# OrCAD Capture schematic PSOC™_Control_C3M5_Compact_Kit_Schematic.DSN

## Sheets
1 07. Revision History: title: KIT_PSC3M5_2GO; rev: 02; note: 630-60706-01
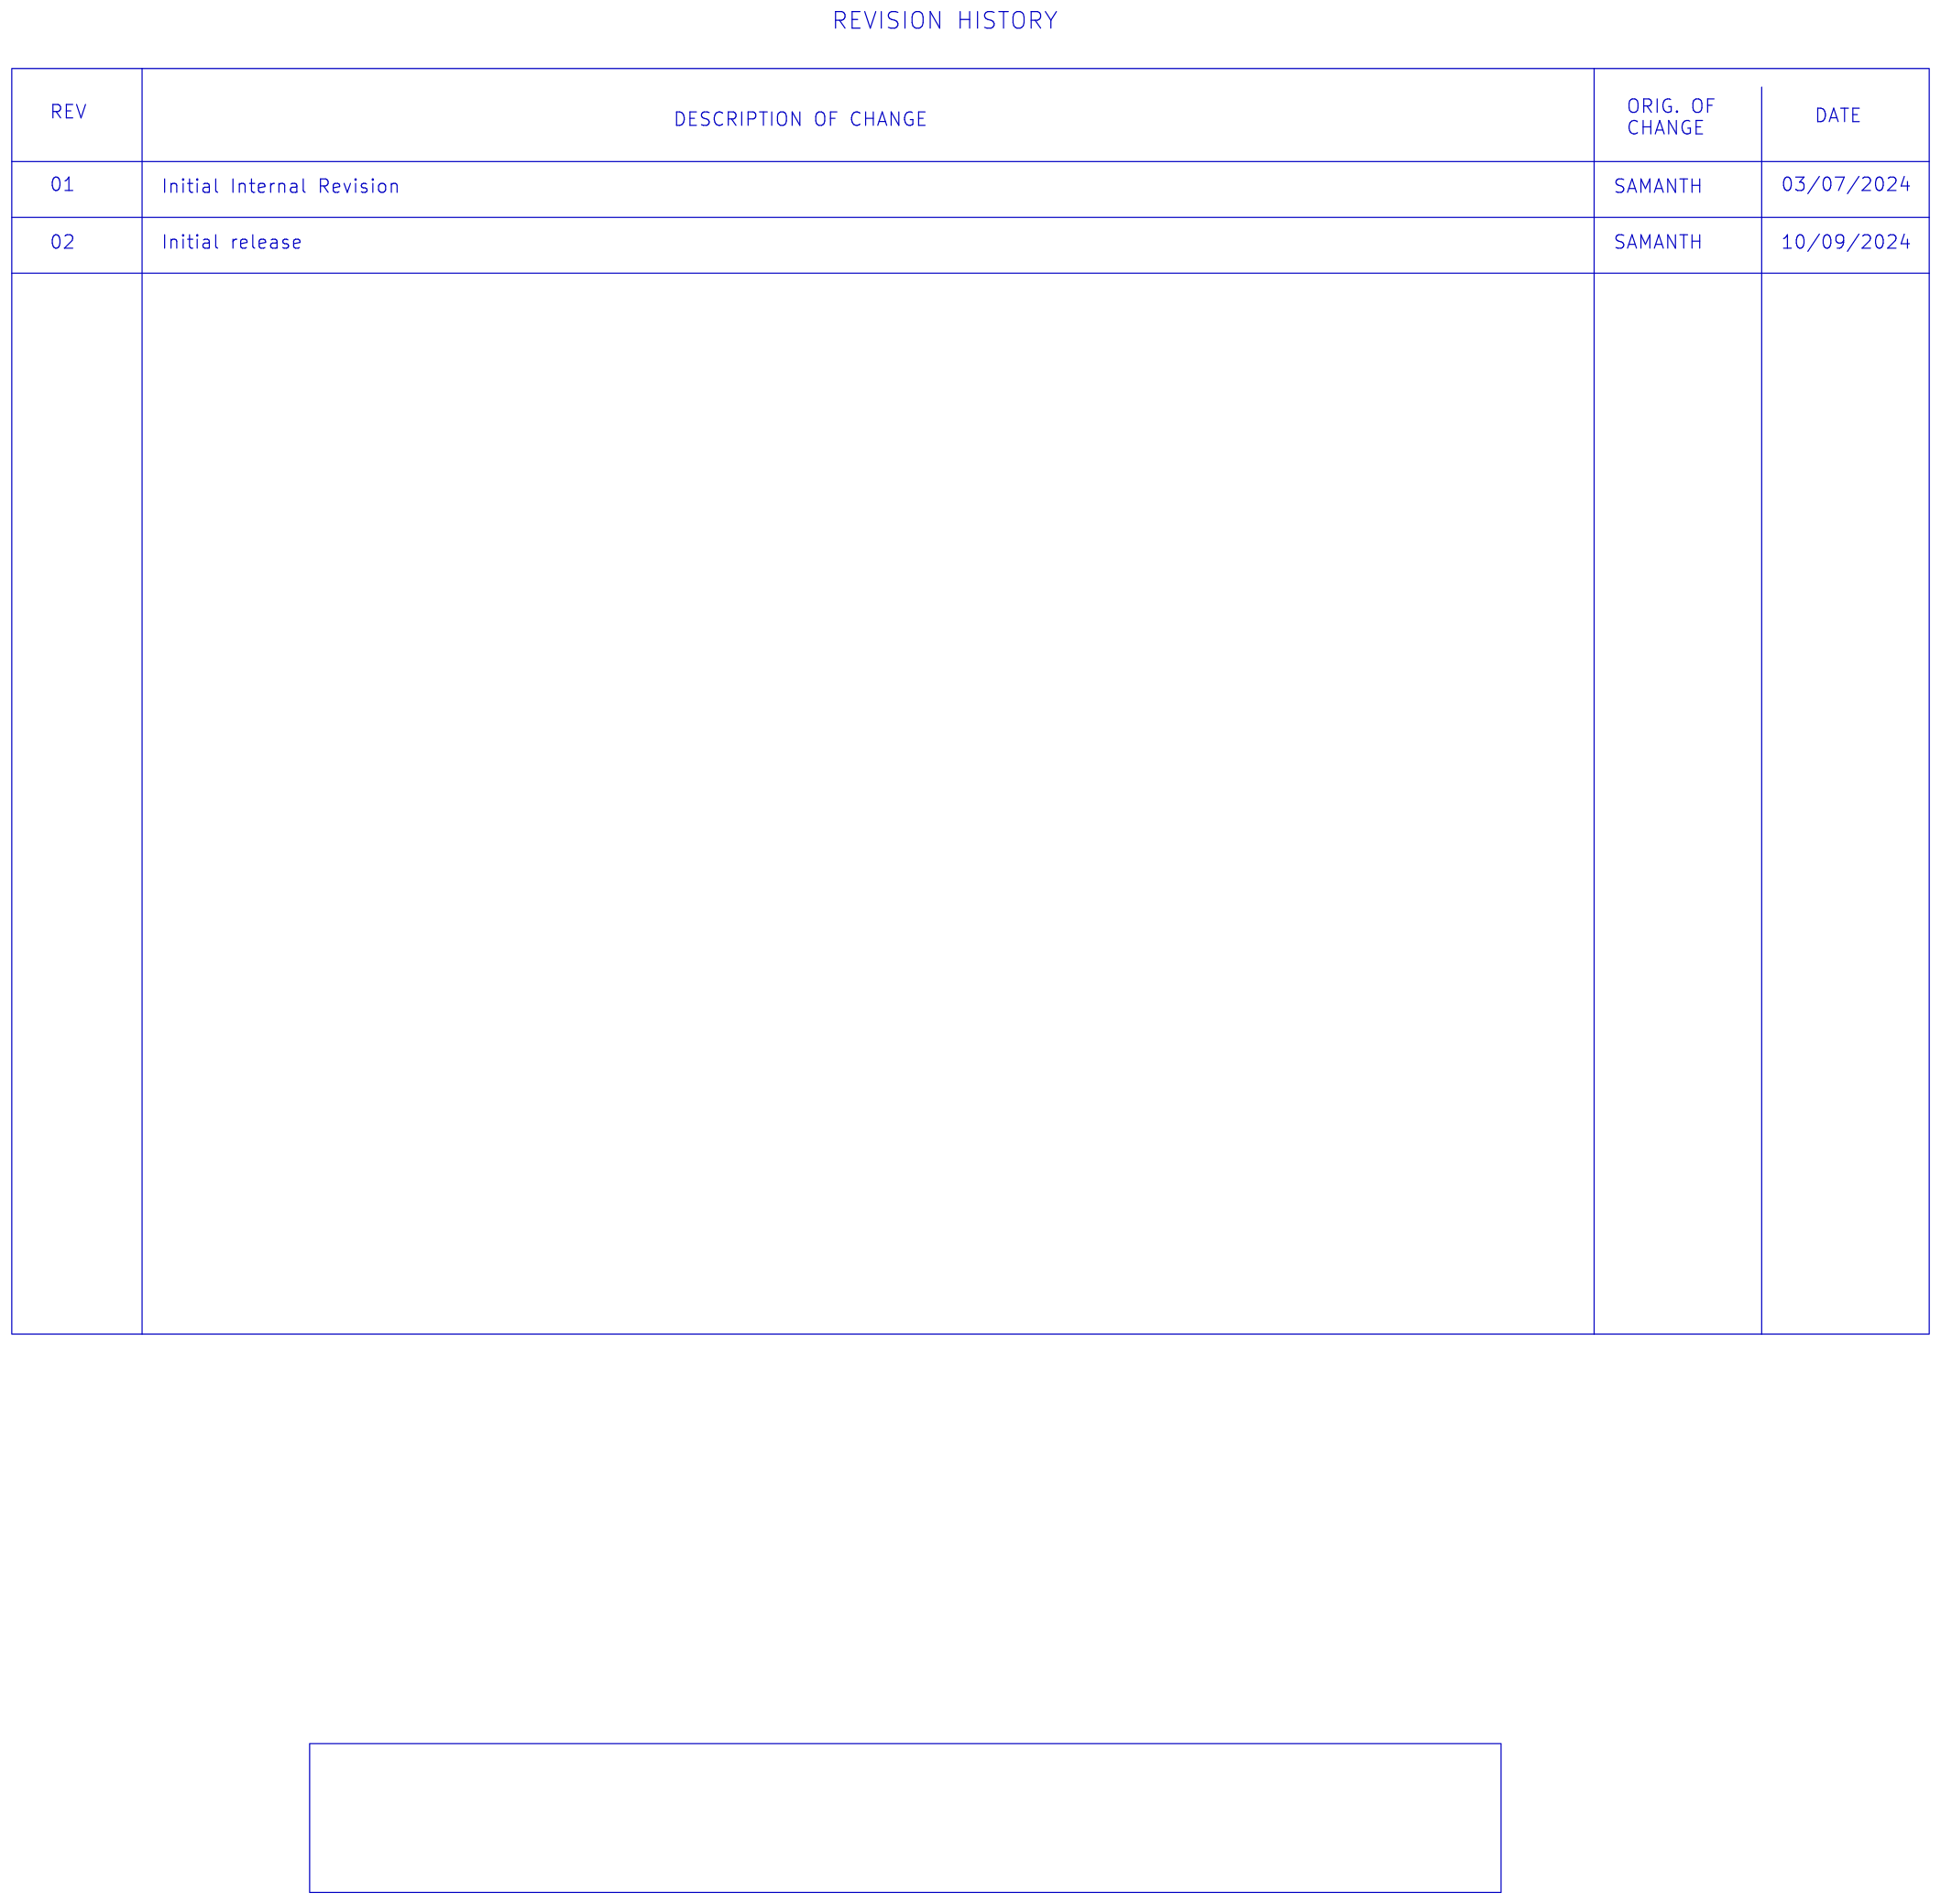
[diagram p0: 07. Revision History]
2 06. Accessories
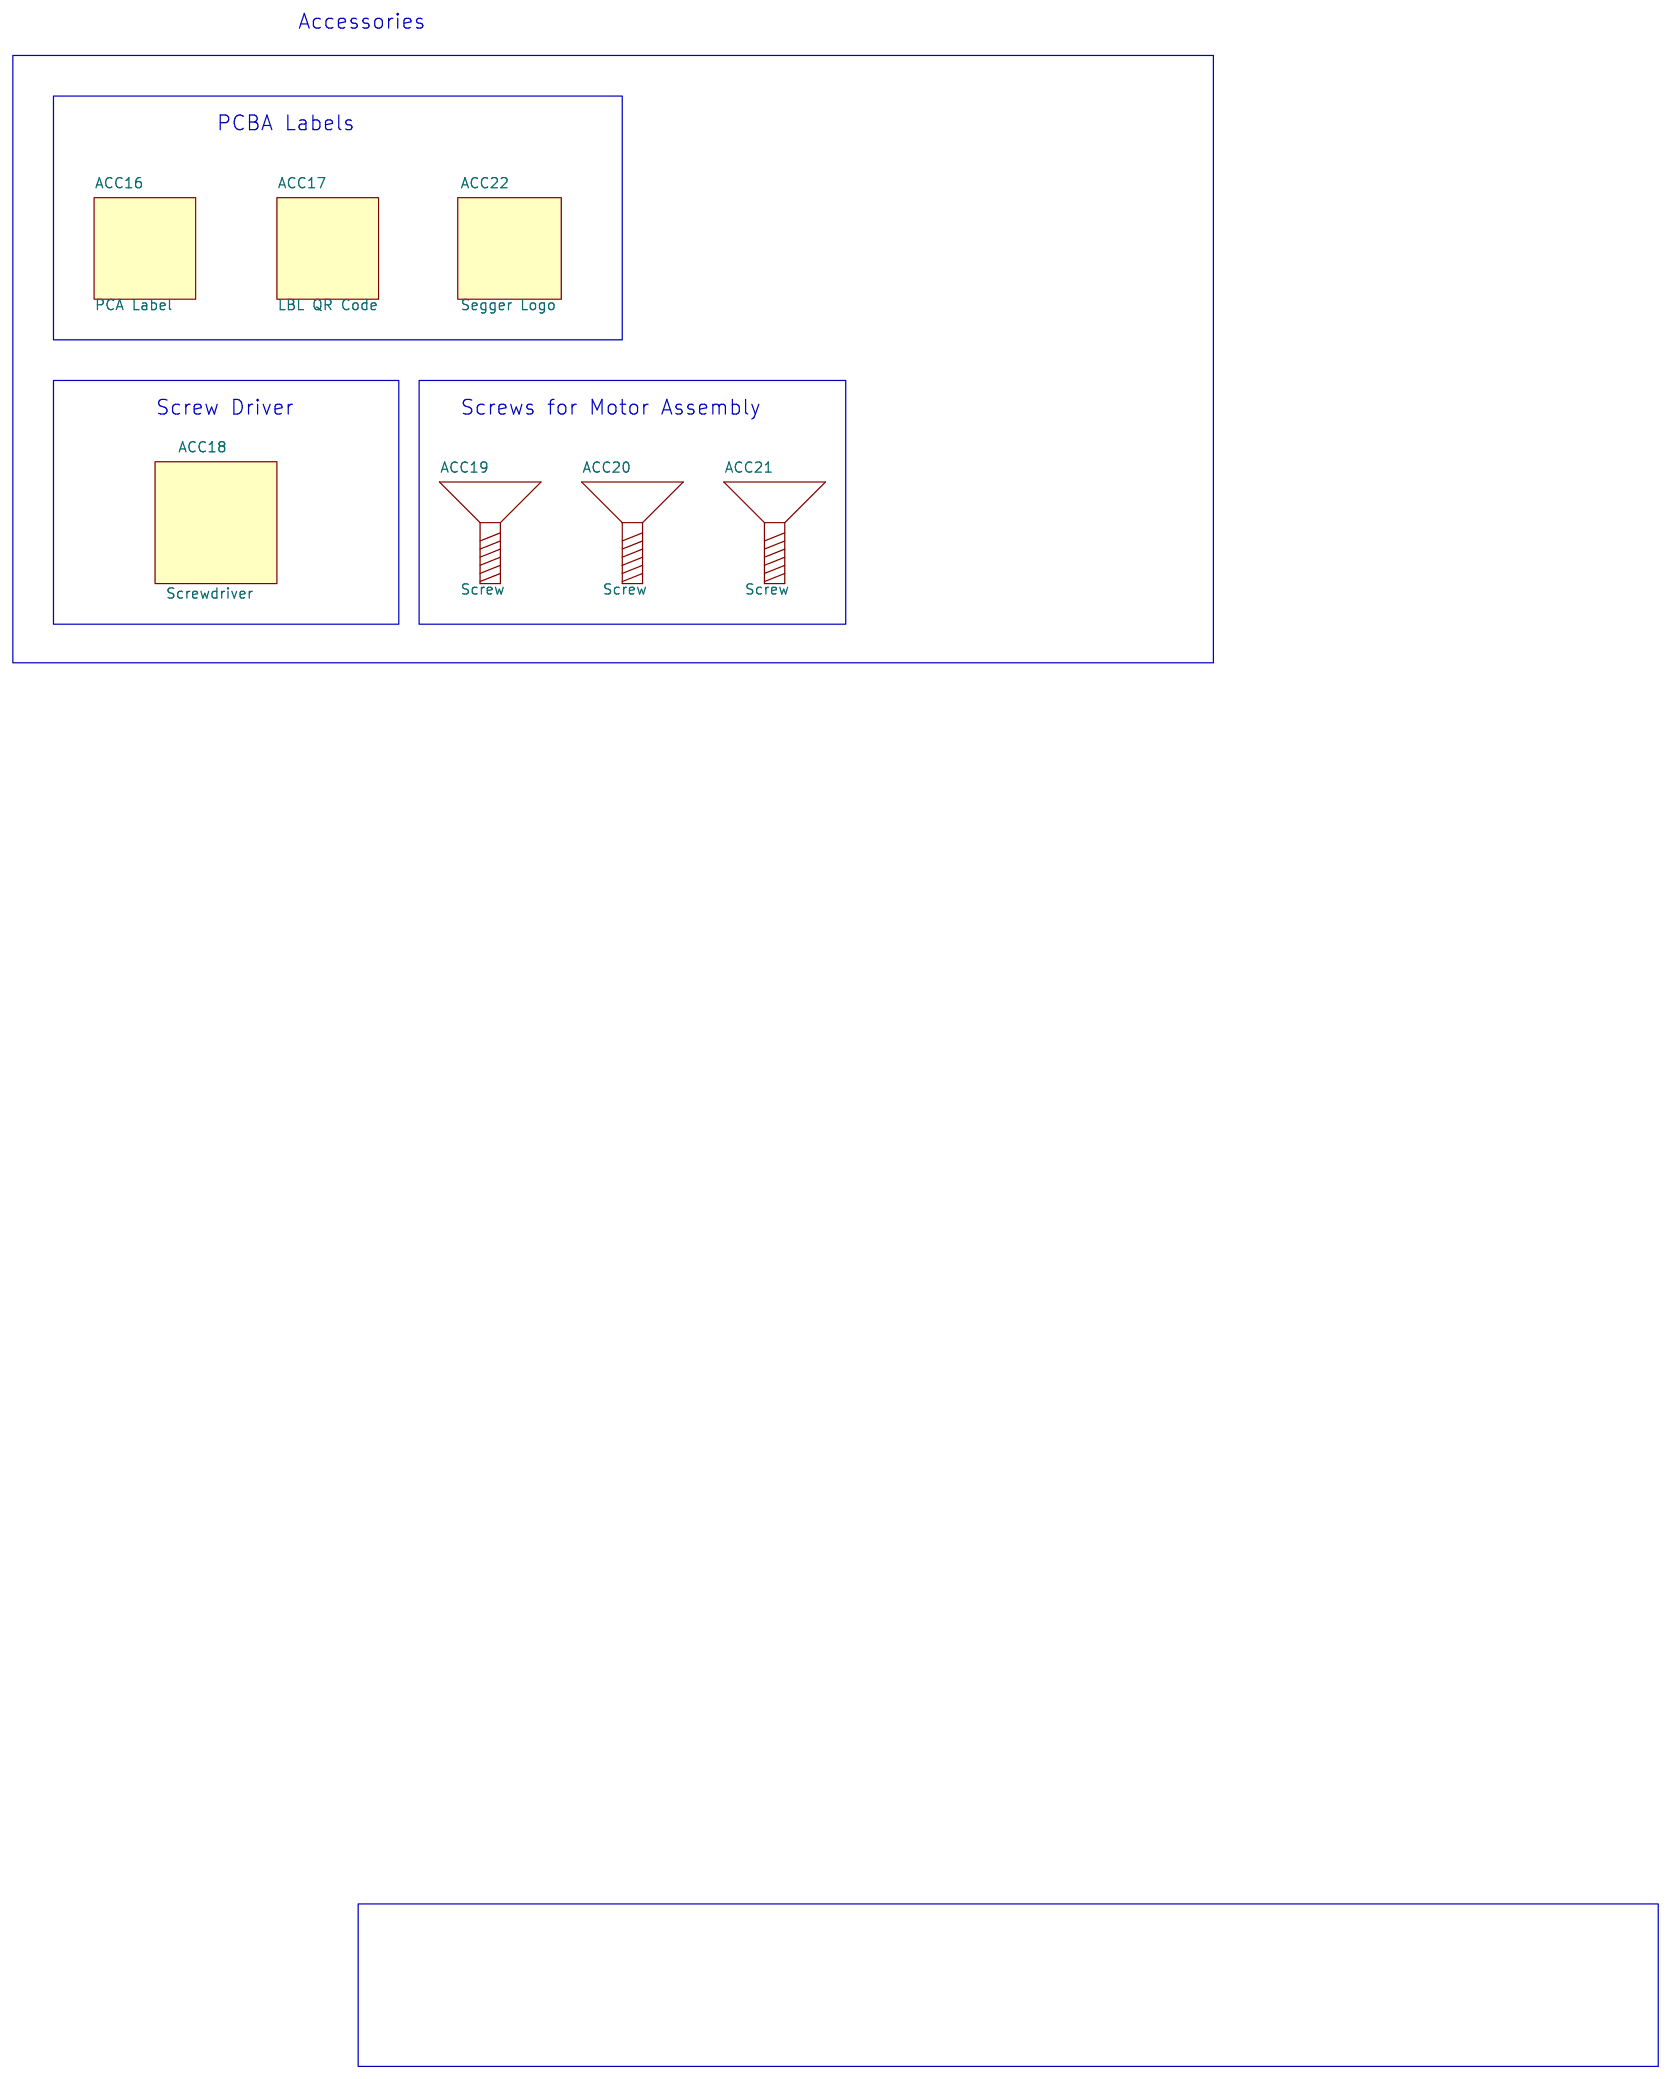
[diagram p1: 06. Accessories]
3 01. Title Page
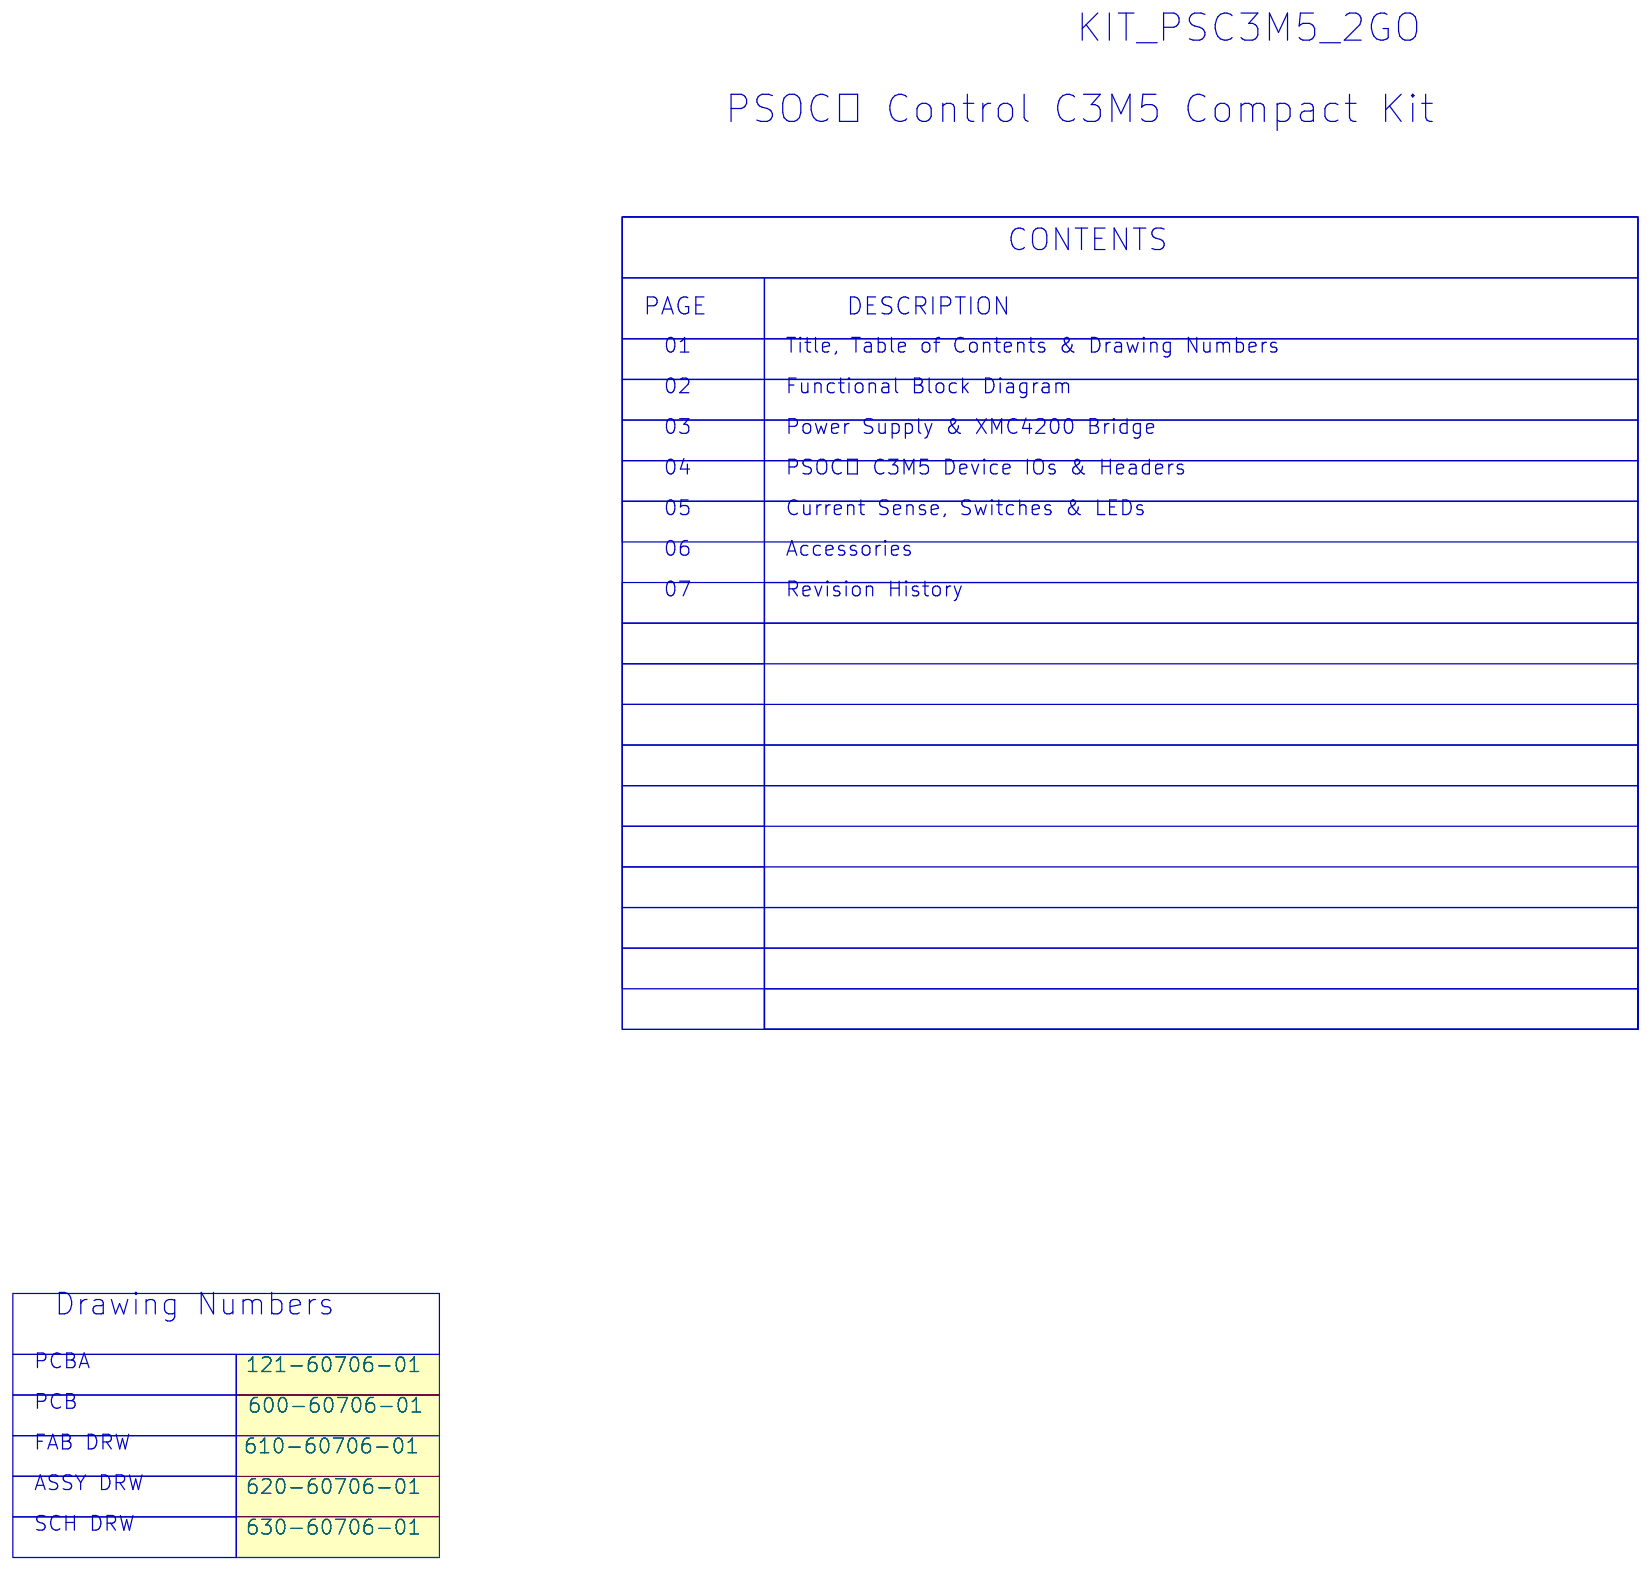
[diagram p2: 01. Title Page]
4 02. Functional Block Diagram
5 03. USB Power & XMC4200 Bridge: size A4
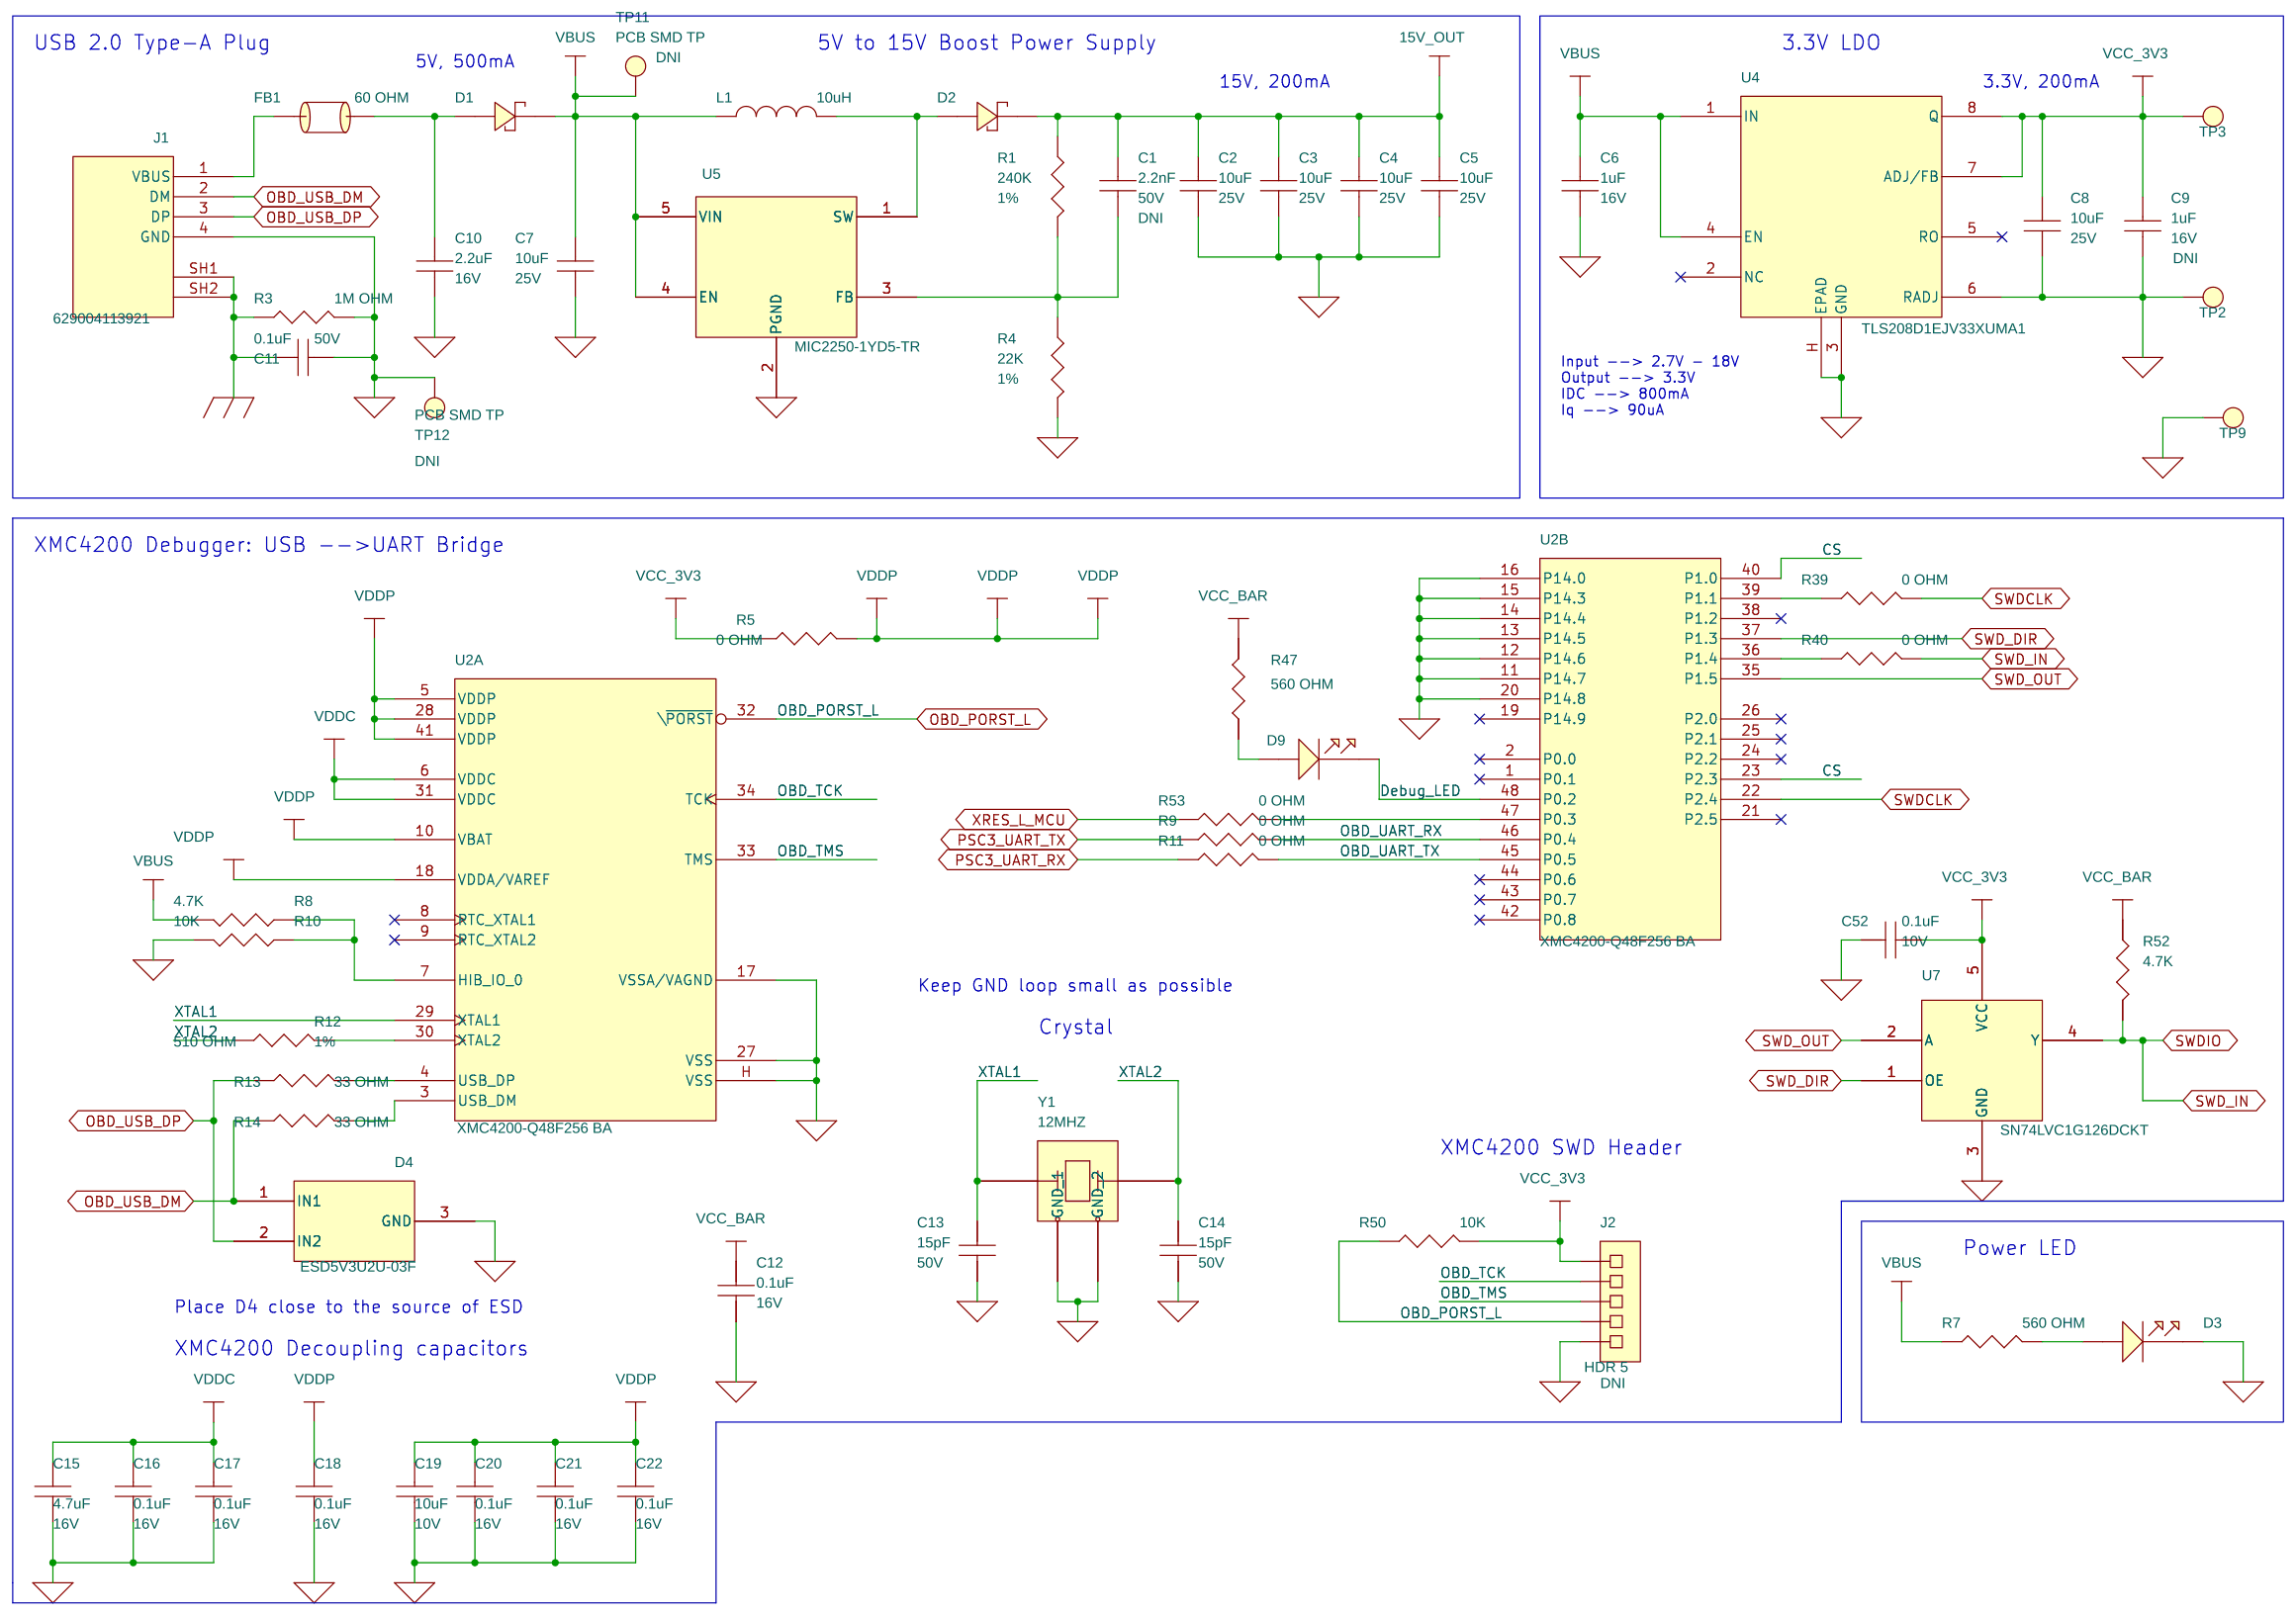
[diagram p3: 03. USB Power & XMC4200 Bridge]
6 04. PSOC C3M5 Device and IPM: size A4
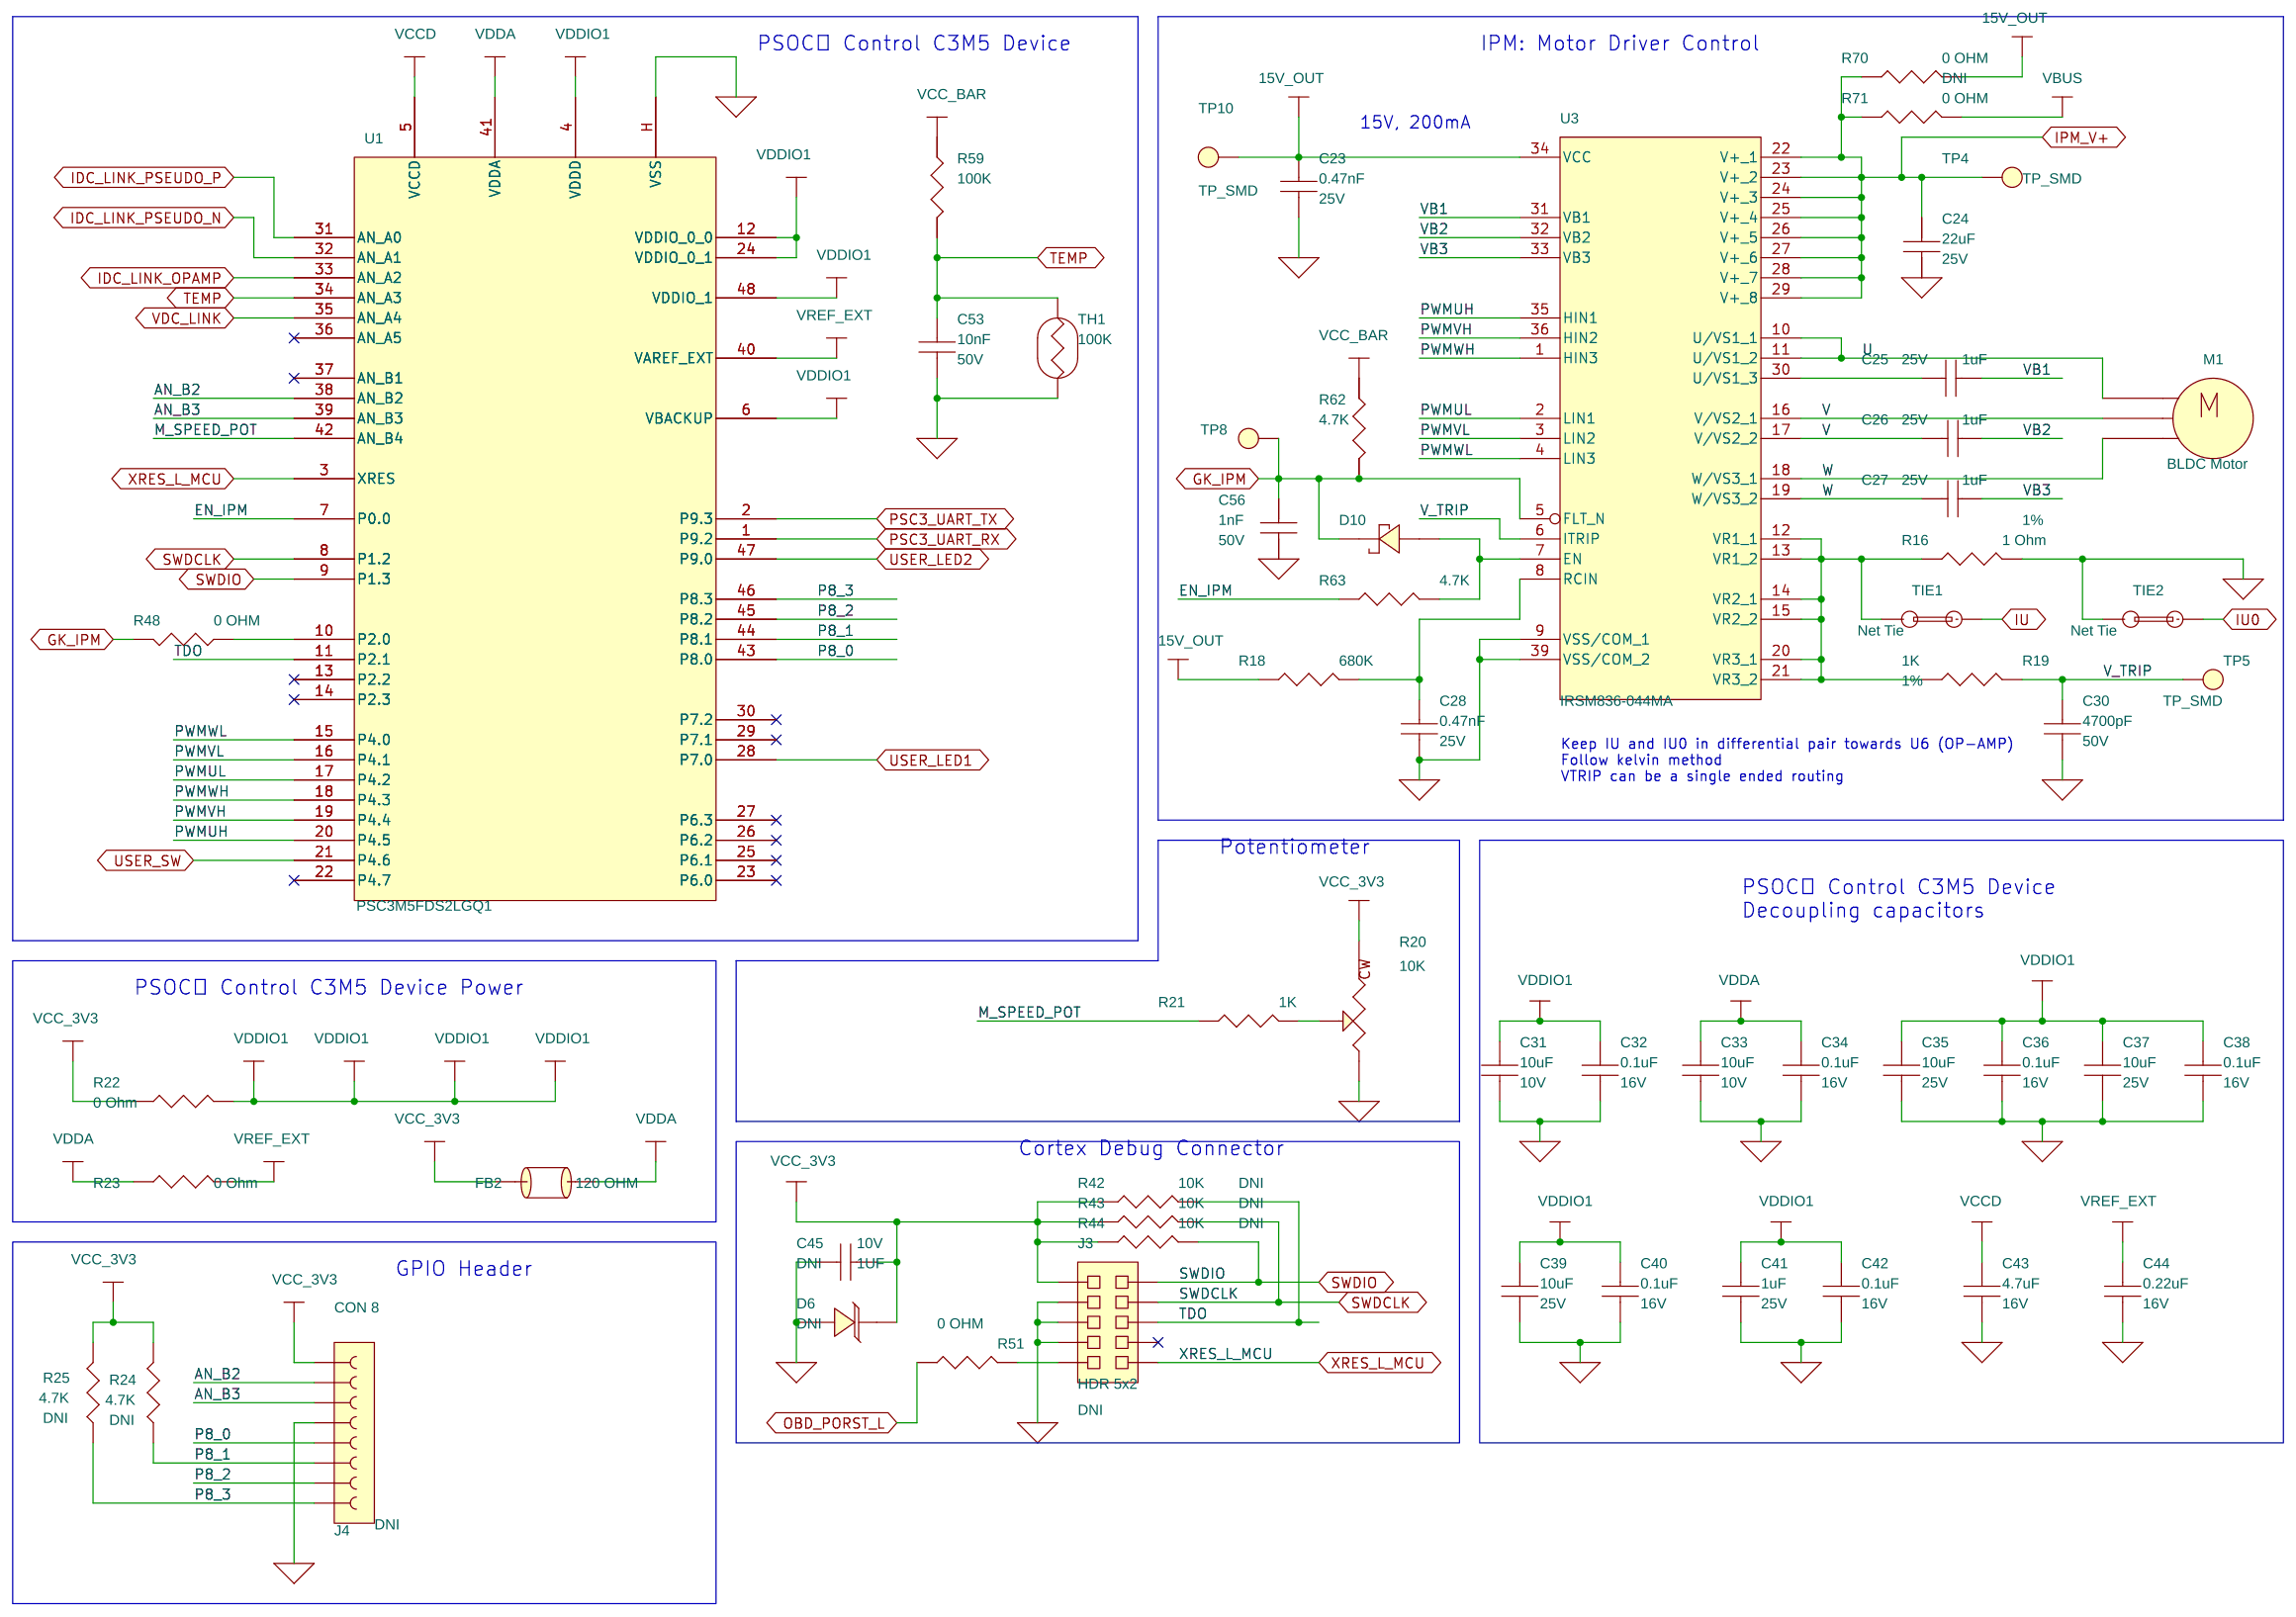
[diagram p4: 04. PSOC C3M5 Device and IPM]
7 05. Current Sense & Peripherals: size A4
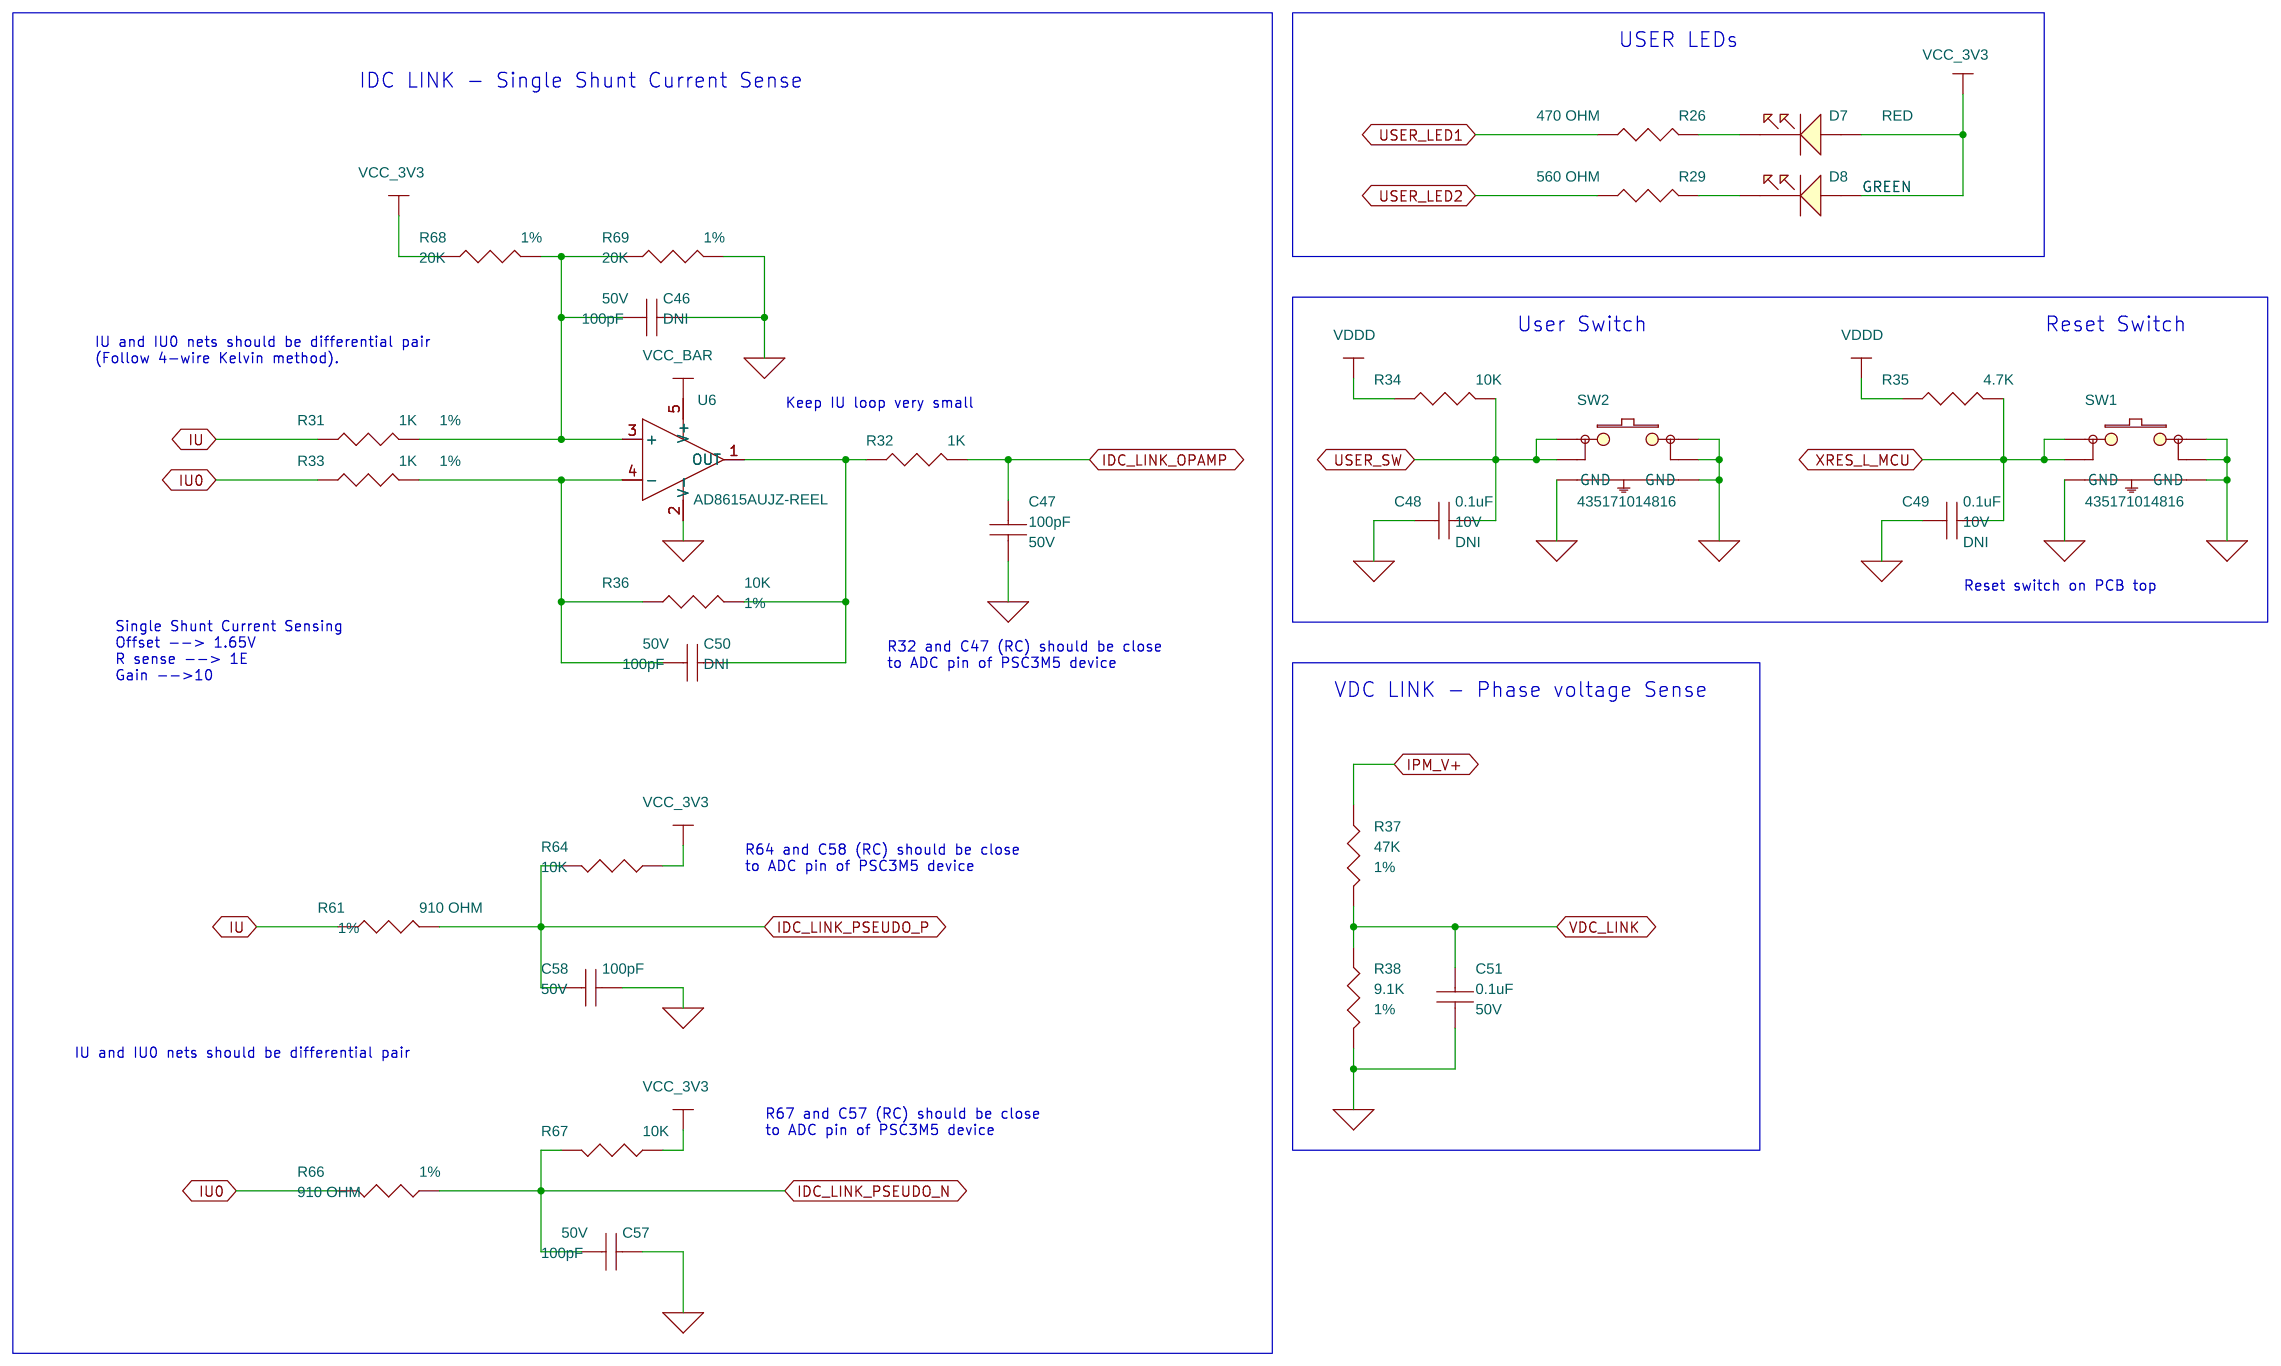
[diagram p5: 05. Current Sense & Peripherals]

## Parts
sheet 01. Title Page
ACC1  121-60706-01  [TBD]
ACC2  600-60706-01  [TBD]
ACC3  610-60706-01  [TBD]
ACC4  620-60706-01  [TBD]
ACC5  630-60706-01  [TBD]
sheet 03. USB Power & XMC4200 Bridge
C1  2.2nF  [CAPC1608_0603M]
C2  10uF  [CAPC2012_0805M]
C3  10uF  [CAPC2012_0805M]
C4  10uF  [CAPC2012_0805M]
C5  10uF  [CAPC2012_0805M]
C6  1uF  [CAPC1608_0603M]
C7  10uF  [CAPC1608_0603M]
C8  10uF  [CAPC1608_0603M]
C9  1uF  [CAPC1608_0603M]
C10  2.2uF  [CAPC1005_0402M]
C11  0.1uF  [CAPC1005_0402M]
C12  0.1uF  [CAPC1005_0402M]
C13  15pF  [CAPC1005_0402M]
C14  15pF  [CAPC1005_0402M]
C15  4.7uF  [CAPC1608_0603M]
C16  0.1uF  [CAPC1005_0402M]
C17  0.1uF  [CAPC1005_0402M]
C18  0.1uF  [CAPC1005_0402M]
C19  10uF  [CAPC1005_0402M]
C20  0.1uF  [CAPC1005_0402M]
C21  0.1uF  [CAPC1005_0402M]
C22  0.1uF  [CAPC1005_0402M]
C52  0.1uF  [CAPC0603_0201N]
D1  SCHOTTKY DIODE  [SOD2512X110N]
D2  SCHOTTKY DIODE  [SOD2512X110N]
D3  150060VS75000  [LEDC1608_0603M]
D4  ESD5V3U2U-03F  [SOTFL40P120X59-3N]
D9  150060VS75000  [LEDC1608_0603M]
FB1  60 OHM  [INDC1608_0603N]
J1  629004113921  [WURTH_629004113921]
J2  HDR 5  [CTST254P1X05_W260]
L1  10uH  [IND_74479887310A]
R1  240K  [RESC1608_0603M]
R3  1M OHM  [RESC1005_0402M]
R4  22K  [RESC1005_0402M]
R5  0 OHM  [RESC1005_0402M]
R7  560 OHM  [RESC0603_0201N]
R8  4.7K  [RESC1608_0603M]
R9  0 OHM  [RESC1005_0402M]
R10  10K  [RESC1608_0603M]
R11  0 OHM  [RESC1005_0402M]
R12  510 OHM  [RESC1005_0402M]
R13  33 OHM  [RESC1005_0402M]
R14  33 OHM  [RESC1005_0402M]
R39  0 OHM  [RESC1005_0402M]
R40  0 OHM  [RESC1005_0402M]
R47  560 OHM  [RESC0603_0201N]
R50  10K  [RESC0603_0201N]
R52  4.7K  [RESC0603_0201N]
R53  0 OHM  [RESC1005_0402M]
TP2  TP_SMD  [tp102c]
TP3  TP_SMD  [tp102c]
TP9  TP_SMD  [tp102c]
TP11  PCB SMD TP  [TP_SMD_SQ_127MM]
TP12  PCB SMD TP  [TP_SMD_SQ_127MM]
U2  XMC4200-Q48F256 BA  [QFN50P700X700X90-49N_NOFID]  (sections A,B)
U4  TLS208D1EJV33XUMA1  [SOIC127P600X170-8_H265X300N]
U5  MIC2250-1YD5-TR  [SOT95P280X110-5N]
U7  SN74LVC1G126DCKT  [SOT65P210X110-6N_TI]
Y1  12MHZ  [OSCCC200X250X60-4N_ECS]
sheet 04. PSOC C3M5 Device and IPM
C23  0.47nF  [CAPC1005_0402M]
C24  22uF  [CAPC2012_0805M]
C25  1uF  [CAPC1608_0603M]
C26  1uF  [CAPC1608_0603M]
C27  1uF  [CAPC1608_0603M]
C28  0.47nF  [CAPC1005_0402M]
C30  4700pF  [CAPC1005_0402M]
C31  10uF  [CAPC1005_0402M]
C32  0.1uF  [CAPC1005_0402M]
C33  10uF  [CAPC1005_0402M]
C34  0.1uF  [CAPC1005_0402M]
C35  10uF  [CAPC1608_0603M]
C36  0.1uF  [CAPC1005_0402M]
C37  10uF  [CAPC1608_0603M]
C38  0.1uF  [CAPC1005_0402M]
C39  10uF  [CAPC1608_0603M]
C40  0.1uF  [CAPC1005_0402M]
C41  1uF  [CAPC1005_0402M]
C42  0.1uF  [CAPC1005_0402M]
C43  4.7uF  [CAPC1608_0603M]
C44  0.22uF  [CAPC1005_0402M]
C45  1UF  [CAPC0603_0201N]
C53  10nF  [CAPC1005_0402M]
C56  1nF  [CAPC1005_0402M]
D6  ESD5V0D5-TP  [sodfl1608x77m]
D10  SCHOTTKY DIODE  [SOD2512X110N]
FB2  120 OHM  [INDC1005_0402M]
J3  HDR 5x2  [SAMTEC_FTSH-105-01-L-DV-K-P-TR]
J4  CON 8  [RTST254P1X08_W265]
M1  BLDC Motor  [MOTOR_1103_KV2230]
R16  1 Ohm  [RESC3225X70N]
R18  680K  [RESC1005_0402M]
R19  1K  [RESC1005_0402M]
R20  10K  [POT_ST-32ETB]
R21  1K  [RESC1005_0402M]
R22  0 Ohm  [RESC1608_0603M]
R23  0 Ohm  [RESC1608_0603M]
R24  4.7K  [RESC1005_0402M]
R25  4.7K  [RESC1005_0402M]
R42  10K  [RESC0603_0201N]
R43  10K  [RESC0603_0201N]
R44  10K  [RESC0603_0201N]
R48  0 OHM  [RESC1005_0402M]
R51  0 OHM  [RESC0603_0201N]
R59  100K  [RESC0603_0201N]
R62  4.7K  [RESC1005_0402M]
R63  4.7K  [RESC1005_0402M]
R70  0 OHM  [RESC1005_0402M]
R71  0 OHM  [RESC1005_0402M]
TH1  100K  [RESC1005_0402M]
TIE1  Net Tie  [net_tie_coppertrace]
TIE2  Net Tie  [net_tie_coppertrace]
TP4  TP_SMD  [tp102c]
TP5  TP_SMD  [ict_tp_smd_030rd_nsp]
TP8  TP_SMD  [ict_tp_smd_030rd_nsp]
TP10  TP_SMD  [tp102c]
U1  PSC3M5FDS2LGQ1  [VQFN40P600X600X90-49N_NOFID]
U3  IRSM836-044MA  [PQFN65P1200X1200X100-36N_INFINEON]
sheet 05. Current Sense & Peripherals
C46  100pF  [CAPC1005_0402M]
C47  100pF  [CAPC1005_0402M]
C48  0.1uF  [CAPC0603_0201N]
C49  0.1uF  [CAPC0603_0201N]
C50  100pF  [CAPC1005_0402M]
C51  0.1uF  [CAPC1005_0402M]
C57  100pF  [CAPC1005_0402M]
C58  100pF  [CAPC1005_0402M]
D7  RED  [LEDC1608X71N_WURTH]
D8  150060VS75000  [LEDC1608_0603M]
R26  470 OHM  [RESC1005_0402M]
R29  560 OHM  [RESC0603_0201N]
R31  1K  [RESC1005_0402M]
R32  1K  [RESC1005_0402M]
R33  1K  [RESC1005_0402M]
R34  10K  [RESC0603_0201N]
R35  4.7K  [RESC0603_0201N]
R36  10K  [RESC1005_0402M]
R37  47K  [RESC1005_0402M]
R38  9.1K  [RESC1005_0402M]
R61  910 OHM  [RESC1005_0402M]
R64  10K  [RESC1005_0402M]
R66  910 OHM  [RESC1005_0402M]
R67  10K  [RESC1005_0402M]
R68  20K  [RESC1005_0402M]
R69  20K  [RESC1005_0402M]
SW1  435171014816  [SW_435171014816]
SW2  435171014816  [SW_435171014816]
U6  AD8615AUJZ-REEL  [SOT95P280X110-5N]
sheet 06. Accessories
ACC16  PCA Label  [TBD]
ACC17  LBL QR Code  [TBD]
ACC18  Screwdriver  [TBD]
ACC19  Screw  [TBD]
ACC20  Screw  [TBD]
ACC21  Screw  [TBD]
ACC22  Segger Logo  [TBD]

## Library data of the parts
ACC1 = PCB: ASSY, PCBA,PSoC Control C3M5 Compact Kit; DNI: DNI; Manufacturer: Cypress Approved CM; Manufacturer_PN: -NA-; Mfr_Name: Cypress Approved CM; Mfr_Part#: -NA-; Mfr_Part_Number: -NA-
ACC2 = PCB: PCB, BARE, PSoC Control C3M5 Compact Kit; DNI: DNI; Manufacturer: Cypress Approved CM; Manufacturer_PN: -NA-; Mfr_Name: Cypress Approved CM; Mfr_Part#: -NA-; Mfr_Part_Number: -NA-
ACC3 = PCB: DRW, FABRICATION DRAWING,PSoC Control C3M5 Compact Kit; DNI: DNI; Manufacturer: -NA-; Manufacturer_PN: -NA-; Mfr_Name: -NA-; Mfr_Part#: -NA-; Mfr_Part_Number: -NA-
ACC4 = PCB: DRW, ASSEMBLY DRAWING, PSoC Control C3M5 Compact Kit; DNI: DNI; Manufacturer: -NA-; Manufacturer_PN: -NA-; Mfr_Name: -NA-; Mfr_Part#: -NA-; Mfr_Part_Number: -NA-
ACC5 = PCB: DRW, SCHEMATIC DRAWING, PSoC Control C3M5 Compact Kit; DNI: DNI; Manufacturer: -NA-; Manufacturer_PN: -NA-; Mfr_Name: -NA-; Mfr_Part#: -NA-; Mfr_Part_Number: -NA-
C1 = CAP-NP: CAP, CER, 2.2nF, 5%, NP0, 50V, 0603; CY_PN: 510-60036-01; DNI: DNI; Device_File: 510-60036-01; Dielectric: NP0; FPLIST: CAPC1608_0603N,CAPC1608_0603M; Lifecycle: Active; Manufacturer: Murata; Manufacturer_PN: GRM1885C1H222JA01D; Operating_Temp: -55°C to 125°C; Package: 0603; Part_Status: In Prod; Tolerance: 5%; Voltage: 50V
C2-C5 = CAP-NP: CAP, CER, 10uF, 10%, X5R, 25V, 0805; Approved: Approved; CY_PN: 510-60052-01; Device_File: 510-60052-01; Dielectric: X5R; FPLIST: CAPC2012_0805N,CAPC2012_0805M; Lifecycle: Active; Manufacturer: Wurth; Manufacturer_PN: 885012107027; Operating_Temp: -55°C ~ 85°C; Package: 0805; Part_Status: Unrel; Tolerance: 10%; Voltage: 25V
C6 = CAP-NP: CAP, CER, 1uF, 10%, X7R, 16V, 0603; Approved: Approved; CY_PN: 510-60715-01; Device_File: 510-60715-01; Dielectric: X7R; FPLIST: CAPC1608_0603N,CAPC1608_0603M; Lifecycle: Active; Manufacturer: Wurth; Manufacturer_PN: 885012206052; Operating_Temp: -55°C ~ 125°C; Package: 0603; Part_Status: Unrel; Tolerance: 10%; Voltage: 16V
C7 = CAP-NP: CAP, CER, 10uF, 20%, X5R, 25V, 0603; Approved: Approved; CY_PN: 510-60180-01; Device_File: 510-60180-01; Dielectric: X5R; FPLIST: CAPC1608_0603N,CAPC1608_0603M; Lifecycle: Active; Manufacturer: Wurth; Manufacturer_PN: 885012106031; Operating_Temp: -55°C ~ 85°C; Package: 0603; Part_Status: In Prod; Tolerance: 20%; Voltage: 25V
C8 C35 C37 C39 = CAP-NP: CAP, CER, 10uF, 20%, X5R, 25V, 0603; Approved: Approved; CY_PN: 510-60180-01; Device_File: 510-60180-01; Dielectric: X5R; FPLIST: CAPC1608_0603N,CAPC1608_0603M; Lifecycle: Active; Manufacturer: Wurth; Manufacturer_PN: 885012106031; Operating_Temp: -55°C to 85°C; Package: 0603; Part_Status: In Prod; Tolerance: 20%; Voltage: 25V
C9 = CAP-NP: CAP, CER, 1uF, 10%, X5R, 16V, 0603; CY_PN: 510-60491-01; DNI: DNI; Device_File: 510-60491-01; Dielectric: X5R; FPLIST: CAPC1608_0603N,CAPC1608_0603M; Lifecycle: Active; Manufacturer: Yageo; Manufacturer_PN: CC0603KRX5R7BB105; Operating_Temp: -55°C to 85°C; Package: 0603; Part_Status: In Des; Tolerance: 10%; Voltage: 16V
C10 = CAP-NP: CAP, CER, 0402, 2.2uF, 10%, 16V, X5R; Approved: Approved; CY_PN: 510-60961-01; Device_File: 510-60961-01; Dielectric: X5R; FPLIST: CAPC1005_0402N,CAPC1005_0402M,capc1005_is0402q; Lifecycle: Active; Manufacturer: Murata; Manufacturer_PN: GRM155R61C225KE11D; Operating_Temp: -55°C ~ 85°C; Package: 0402; Part_Status: Unrel; Tolerance: 10%; Voltage: 16V
C11 C51 = CAP-NP: CAP, CER, 0.1uF, 10%, X7R, 50V, 0402; Approved: Approved; CY_PN: 510-60335-01; Device_File: 510-60335-01; Dielectric: X7R; FPLIST: CAPC1005_0402N,CAPC1005_0402M; Lifecycle: Active; Manufacturer: Wurth; Manufacturer_PN: 885012205086; Operating_Temp: -55°C ~ 125°C; Package: 0402; Part_Status: Unrel; Tolerance: 10%; Voltage: 50V
C12 C16-C18 C20-C22 = CAP-NP: CAP, CER, 0.1uF, 10%, X7R, 16V, 0402; Approved: Approved; CY_PN: 510-60878-01; Device_File: 510-60878-01; Dielectric: X7R; FPLIST: CAPC1005_0402N,CAPC1005_0402M; Lifecycle: Active; Manufacturer: Wurth; Manufacturer_PN: 885012205037; Operating_Temp: - 55 C to + 125 C; Package: 0402; Part_Status: In prod; Tolerance: 10%; Voltage: 16V
C13 C14 = CAP-NP: CAP, CER, 15pF, 5%, 50V, NPO, 0402; Approved: Approved; CY_PN: 510-60306-01; Device_File: 510-60306-01; Dielectric: NPO; FPLIST: CAPC1005_0402N,CAPC1005_0402M; Lifecycle: Active; Manufacturer: Wurth; Manufacturer_PN: 885012005056; Operating_Temp: -55°C ~ 125°C; Package: 0402; Part_Status: Unrel; Tolerance: 5%; Voltage: 50V
C15 C43 = CAP-NP: CAP, CER, 4.7uF, 10%, X5R, 16V, 0603; CY_PN: 510-60058-01; Device_File: 510-60058-01; Dielectric: X5R; FPLIST: CAPC1608_0603N,CAPC1608_0603M; Lifecycle: Active; Manufacturer: Murata; Manufacturer_PN: GRM185R61C475KE11D; Operating_Temp: -55°C to 85°C; Package: 0603; Part_Status: In Prod; Tolerance: 10%; Voltage: 16V
C19 C31 C33 = CAP-NP: CAP, CER, 10uF, 20%, X5R, 10V, 0402; Approved: Approved; CY_PN: 510-60337-01; Device_File: 510-60337-01; Dielectric: X5R; FPLIST: CAPC1005_0402N,CAPC1005_0402M; Lifecycle: Active; Manufacturer: Wurth; Manufacturer_PN: 885012105022; Operating_Temp: -55°C ~ 85°C; Package: 0402; Part_Status: Unrel; Tolerance: 20%; Voltage: 10V
C52 = CAP-NP: CAP, CER, 0.1uF, 20%, X5R, 10V, 0201; Approved: Approved; CY_PN: 510-60777-01; Device_File: 510-60777-01; Dielectric: X5R; FPLIST: CAPC0603_0201N,CAPC0603_0201Q; Lifecycle: Active; Manufacturer: Wurth; Manufacturer_PN: 885012104002; Operating_Temp: -55°C ~ 85°C; Package: 0201; Part_Status: In Prod; Tolerance: 20%; Voltage: 10V
D1 D2 D10 = DIO-SCHOTTKY: DIO, INFINEON, SCHOTTKY, 30V, 1A, SOD323-2; Approved: Approved; CY_PN: BAS3010A03WE6327HTSA1; Device_File: BAS3010A03WE6327HTSA1; Lifecycle: Active; Manufacturer: Infineon; Manufacturer_PN: BAS3010A03WE6327HTSA1; Operating_Temp: -65°C ~ 125°C; Package: SOD-323; Part_Status: Unrel; Rating: 1A; Voltage: 30V
D3 D8 D9 = DIO-LED: LED, Green, Clear, 574nm, 2V, 0603; CY_PN: 534-60054-01; Device_File: 534-60054-01; FPLIST: LEDC1608_0603M,LEDC1608_0603N; Lifecycle: Active; Manufacturer: Wurth; Operating_Temp: -55°C to 85°C; Package: 0603; Part_Status: In Des; Rating: NA; Voltage: 2V
D4 = ESD5V3U2U-03F: DIO, INFINEON, ESD Protection, 5.3V, 2CH, +/-20KV, SOT-723; Approved: Approved; Lifecycle: Active; Manufacturer: Infineon; Operating_Temp: -40°C ~ 125°C; Package: SOT-723; Part_Status: Unrel; Rating: +/-20KV, 3A; Voltage: 5.3V
FB1 = FB: IND, FERRITE BEAD, CHIP, 60-OHM, 2A, 0603; Approved: Approved; CY_PN: 520-60342-01; Current: 2A; DB_Status: Verified; Device_File: 520-60342-01; Lifecycle: Active; Manufacturer: Wurth; Manufacturer_PN: 742792602; Material: Ferrite; Operating_Temp: -55°C ~ 125°C; Package: 0603; Part_Status: Unrel; Part_Type: Ferrite bead; Tolerance: 25%
J1 = USB-TYPE_A-2SH: CONN, USB 2.0 PLUG, TYPE-A, 4POS, SMD, RA; Approved: Approved; CY_PN: 720-60704-01; Conatct_Length: NA; Contact_Finish: Gold; Current_Rating: 1.5A; Device_File: 720-60704-01; Lifecycle: Active; Manufacturer: Wurth; Mated_Height: NA; Operating_Temp: -40°C ~ 105°C; Part_Status: Unrel; Pin_Pitch: NA; Pins: 4; Row_pitch: NA; Rows: 1; Shrouding: NA
J2 = PLG-5-J: CONN, HDR, MALE, SINGLE, 5POS, 2.54mm, GOLD, STR, TH; Approved: Approved; CY_PN: 720-60218-01; Conatct_Length: 5.84mm; Contact_Finish: GOLD; Current_Rating: 3A; DNI: DNI; Device_File: 720-60218-01; Lifecycle: Active; Manufacturer: Sullins; Manufacturer_PN: PRPC005SAAN-RC; Mated_Height: 8.34mm; Operating_Temp: -40°C to 105°C; Part_Status: InProd; Pin_Pitch: 2.54mm; Pins: 5; Row_pitch: NA; Rows: 1; Shrouding: Unshrouded
L1 = IND: IND, FIXED IND, 10uH, 850mA, 300mOHM, 1008, SMD; Approved: Approved; CY_PN: 520-60319-01; Current: 850mA; DB_Status: Verified; Device_File: 520-60319-01; ESR: 300mOHM; Lifecycle: Active; Manufacturer: Wurth; Manufacturer_PN: 74479887310A; Material: Shielded; Operating_Temp: -40°C ~ 125°C; Package: SMD; Part_Status: Unrel; Part_Type: Inductor; Tolerance: 20%
R1 = RES: RES, 240K OHM, 1%, 1/10W, 0603; Approved: Approved; CY_PN: 500-61350-01; Device_File: 500-61350-01; FPLIST: RESC1608_0603N,RESC1608_0603Q,RESC1608_0603M; Lifecycle: Active; Manufacturer: Yageo; Manufacturer_PN: RC0603FR-07240KL; Operating_Temp: -55°C ~ 155°C; Package: 0603; Part_Status: Unrel; Rating: 1/10W; Tolerance: 1%
R3 = RES: RES, FIXED, 1M OHM, 1%, 100PPM, 1/10W, 0402; Approved: Approved; CY_PN: 500-60247-01; Device_File: 500-60247-01; FPLIST: RESC1005_0402N,RESC1005_0402M; Lifecycle: Active; Manufacturer: Wurth; Manufacturer_PN: 560112110033; Operating_Temp: -55°C ~ 155°C; Package: 0402; Part_Status: unrel; Rating: 1/10W; Tolerance: 1%
R4 = RES: RES, FIXED, 22K OHM, 1%, 1/10W, 0402; Approved: Approved; CY_PN: 500-60497-01; Device_File: 500-60497-01; FPLIST: RESC1005_0402N,RESC1005_0402M; Lifecycle: Active; Manufacturer: Wurth; Manufacturer_PN: 560112110098; Operating_Temp: -55°C ~ 155°C; Package: 0402; Part_Status: unrel; Rating: 1/10W; Tolerance: 1%
R5 R9 R11 R39 R40 R48 R53 R71 = RES: RES, FIXED, 0 OHM, JUMPER, 1A, 1/16W, 0402; Approved: Approved; CY_PN: 500-60344-01; Device_File: 500-60344-01; FPLIST: RESC1005_0402N,RESC1005_0402M; Lifecycle: Active; Manufacturer: Wurth; Manufacturer_PN: 560112110001; Operating_Temp: -55°C ~ 155°C; Package: 0402; Part_Status: In Prod; Rating: 1/16W; Tolerance: JUMPER
R7 R29 R47 = RES: RES, 560 OHM, 5%, 1/20W, 0201; Approved: Approved; CY_PN: 500-61330-01; Device_File: 500-61330-01; FPLIST: RESC0603_0201N,RESC0603_0201Q; Lifecycle: Active; Manufacturer: Yageo; Manufacturer_PN: RC0201JR-07560RL; Operating_Temp: -55°C ~ 125°C; Package: 0201; Part_Status: Unrel; Rating: 1/20W; Tolerance: 5%
R8 = RES: RES, FIXED, 4.7K OHM, 1%, 1/10 W, 0603; Approved: Approved; CY_PN: 500-60404-01; Device_File: 500-60404-01; FPLIST: RESC1608_0603N,RESC1608_0603Q,RESC1608_0603M; Lifecycle: Active; Manufacturer: Wurth; Manufacturer_PN: 560112116006; Operating_Temp: -55°C ~ 155°C; Package: 0603; Part_Status: unrel; Rating: 1/10W; Tolerance: 1%
R10 = RES: RES, Fixed, 10K, 1%, 1/10W, 0603; Approved: Approved; CY_PN: 500-60043-01; Device_File: 500-60043-01; FPLIST: RESC1608_0603N,RESC1608_0603Q,RESC1608_0603M; Lifecycle: Active; Manufacturer: Wurth; Manufacturer_PN: 560112116005; Operating_Temp: -55°C ~ 155°C; Package: 0603; Part_Status: In Prod; Rating: 1/10W; Tolerance: 1%
R12 = RES: RES, FIXED, 510 OHM, 1%, 1/16W, 0402, SMD; Approved: Approved; CY_PN: 500-61407-01; Device_File: 500-61407-01; FPLIST: RESC1005_0402N,RESC1005_0402M; Lifecycle: Active; Manufacturer: Yageo; Manufacturer_PN: RC0402FR-07510RL; Operating_Temp: -55°C ~ 155°C; Package: 0402; Part_Status: unrel; Rating: 1/16W; Tolerance: 1%
R13 R14 = RES: RES, FIXED, 33 OHM, 1%, 1/10W, 0402; Approved: Approved; CY_PN: 500-61403-01; Device_File: 500-61403-01; FPLIST: RESC1005_0402N,RESC1005_0402M; Lifecycle: Active; Manufacturer: Wurth; Manufacturer_PN: 560112110004; Operating_Temp: -55°C ~ 155°C; Package: 0402; Part_Status: unrel; Rating: 1/10W; Tolerance: 1%
R34 R50 = RES: RES, 10K OHM, 1%, 1/20W, 0201; Approved: Approved; CY_PN: 500-61335-01; Device_File: 500-61335-01; FPLIST: RESC0603_0201N,RESC0603_0201Q; Lifecycle: Active; Manufacturer: Yageo; Manufacturer_PN: RC0201FR-0710KL; Operating_Temp: -55°C ~ 125°C; Package: 0201; Part_Status: Unrel; Rating: 1/20W; Tolerance: 1%
R35 R52 = RES: RES, Fixed, 4.7K, 5%, 1/20W, 0201; CY_PN: 500-60979-01; Device_File: 500-60979-01; FPLIST: RESC0603_0201N,RESC0603_0201Q; Lifecycle: Active; Manufacturer: Yageo; Manufacturer_PN: RC0201JR-074K7L; Operating_Temp: -55°C to 125°C; Package: 0201; Part_Status: In Production; Rating: 1/20W; Tolerance: 5%
TP2-TP4 TP9 TP10 = TP_SMD: TestPoint, PCB, Circle, 1mm, SMD; CY_PN: NA; DNI: DNI; Lifecycle: NA; Manufacturer: NA; Manufacturer_PN: NA; Part_Status: NA
TP11 TP12 = TP: TP, TEST POINT, PCB, SQUARE SMD (50x50 mil); Approved: Approved; CY_PN: NA; DNI: DNI; Description1: TP, TEST POINT, PCB, SQUARE SMD (50x50 mil); Device_File: NA; Manufacturer: NA; Manufacturer_PN: NA; Part_Status: NA
U2 = IC_XMC4200-Q48F256: IC, Infineon, MCU, XMC4200, M4, 80MHz, 256KB FLASH, VQFN-48; Approved: Approved; FPLIST: QFN50P700X700X90-49N,QFN50P700X700X90-49N_NOFID; HARD_LOCATION: YES; Lifecycle: Active; Manufacturer: Infineon; Operating_Temp: -40°C to 85°C; Package: VQFN-48; Part_Status: Unrel
U4 = IC_TLS208D1EJV33_0: IC, IFX, REG, LDO, 3.3V, 0.8V-5.25V, 800mA, 8-SOIC; Approved: Approved; HARD_LOCATION: YES; Lifecycle: Active; Manufacturer: Infineon; Operating_Temp: -40°C ~ 150°C; Operating_Voltage: 0.8V-5.25V; Package: 8-SOIC; Part_Status: Unrel
U5 = IC_MIC2250-1YD5: IC, REG, BOOST, 1CH, ADJ, 2.5V-5.5V, 1.24V-32V, 2A, SOT-23-5; Approved: Approved; CY_PN: 450-60486-01; Device_File: 450-60486-01; Lifecycle: Active; Manufacturer: Microchip Technology; Operating_Temp: -40°C ~ 125°C; Operating_Voltage: 2.5V ~ 5.5V; Package: SOT-23-5; Part_Status: Unrel
U7 = IC_SN74LVC1G126DCK: IC, Buffer, Non-Inverting, 1-Bit, 3-State, SOT-353; Approved: Approved; CY_PN: 450-60488-01; Device_File: 450-60488-01; Lifecycle: Active; Manufacturer: Texas Instruments; Operating_Temp: -40°C ~ 125°C (TA); Operating_Voltage: 1.65V-5.5V; Package: SC-70-5; Part_Status: Unrel
Y1 = XTAL-4P-2G4G: CRYSTAL, 12MHZ, ±10ppm, 12PF, SMD; Approved: Approved; CY_PN: 542-60114-01; Device_File: 542-60114-01; Frequency_Stability: 15ppm; Lifecycle: Active; Load_Capacitance: 12pF; Manufacturer: ECS; Manufacturer_PN: ECS-120-12-36Q-CWY-TR; Operating_Temp: -30°C ~ 85°C; Output_Type: NA; Package: SMD; Part_Status: Unrel; Supply_Voltage: NA; Tolerance: 10ppm
C23 C28 = CAP-NP: CAP, CER, 0.47nF, 5%, NP0, 25V, 0402; CY_PN: 510-60778-01; Device_File: 510-60778-01; Dielectric: NP0; FPLIST: CAPC1005_0402N,CAPC1005_0402M; Lifecycle: Active; Manufacturer: Kemet; Manufacturer_PN: C0402C471J3GAC7867; Operating_Temp: -55°C to 125°C; Package: 0402; Part_Status: In Des; Tolerance: 5%; Voltage: 25V
C24 = CAP-NP: CAP, CER, 22uF, 20%, X5R, 25V, 0805; Approved: Approved; CY_PN: 510-60564-01; Device_File: 510-60564-01; Dielectric: X5R; FPLIST: CAPC2012_0805N,CAPC2012_0805M; Lifecycle: Active; Manufacturer: Wurth; Manufacturer_PN: 885012107019; Operating_Temp: -55°C ~ 85°C; Package: 0805; Part_Status: Unrel; Tolerance: 20%; Voltage: 25V
C25-C27 = CAP-NP: CAP, CER, 1uF, 10%, X7R, 25V, 0603; Approved: Approved; CY_PN: 510-60064-01; Device_File: 510-60064-01; Dielectric: X7R; FPLIST: CAPC1608_0603N,CAPC1608_0603M; Lifecycle: Active; Manufacturer: Wurth; Manufacturer_PN: 885012206076; Operating_Temp: -55°C ~ 125°C; Package: 0603; Part_Status: Unrel; Tolerance: 10%; Voltage: 25V
C30 = CAP-NP: CAP, CER, 4700pF, 10%, X7R, 50V, 0402; Approved: Approved; CY_PN: 510-60393-01; Device_File: 510-60393-01; Dielectric: X7R; FPLIST: CAPC1005_0402N,CAPC1005_0402M; Lifecycle: Active; Manufacturer: Wurth; Manufacturer_PN: 885012205065; Operating_Temp: -55°C ~ 125°C; Package: 0402; Part_Status: Unrel; Tolerance: 10%; Voltage: 50V
C32 C34 C36 C38 C40 C42 = CAP-NP: CAP, CER, 0.1uF, 10%, X7R, 16V, 0402; Approved: Approved; CY_PN: 510-60878-01; Device File: 510-60878-01; Device_File: 510-60878-01; Dielectric: X7R; FPLIST: CAPC1005_0402N,CAPC1005_0402M; Lifecycle: Active; Manufacturer: Wurth; Manufacturer_PN: 885012205037; Operating_Temp: - 55 C to + 125 C; Package: 0402; Part Status: In Prod; Part_Status: In prod; Tolerance: 10%; Voltage: 16V
C41 = CAP-NP: CAP, CER, 1uF, 10%, X5R, 25V, 0402; CY_PN: 510-60560-01; Device_File: 510-60560-01; Dielectric: X5R; FPLIST: CAPC1005_0402N,CAPC1005_0402M; Lifecycle: Active; Manufacturer: Murata; Manufacturer_PN: GRM155R61E105KA12D; Operating_Temp: -55°C to 85°C; Package: 0402; Part_Status: In Des; Tolerance: 10%; Voltage: 25V
C44 = CAP-NP: CAP, CER, 0.22uF, 10%, X7R, 16V, 0402; CY_PN: 510-60418-01; Device_File: 510-60418-01; Dielectric: X7R; FPLIST: CAPC1005_0402N,CAPC1005_0402M; Lifecycle: Active; Manufacturer: TDK; Manufacturer_PN: CGA2B2X7R1C224K050BA; Operating_Temp: -55°C to 125°C; Package: 0402; Part_Status: In Prod; Tolerance: 10%; Voltage: 16V
C45 = CAP-NP: CAP, CER, 1UF, 10V, X5R, 0201; Approved: Approved; CY_PN: 510-61118-01; DNI: DNI; Device_File: 510-61118-01; Dielectric: X5R; FPLIST: CAPC0603_0201N,CAPC0603_0201Q; Lifecycle: Active; Manufacturer: YAEGO; Manufacturer_PN: CC0201MRX5R6BB105; Operating_Temp: -55°C ~ 85°C; Package: 0201; Part_Status: In Prod; Tolerance: 20%; Voltage: 10V
C53 = CAP-NP: CAP, CER, 10nF, 10%, X7R, 50V, 0402; Approved: Approved; CY_PN: 510-60089-01; Device_File: 510-60089-01; Dielectric: X7R; FPLIST: CAPC1005_0402N,CAPC1005_0402M; Lifecycle: Active; Manufacturer: Wurth; Manufacturer_PN: 885012205067; Operating_Temp: -55°C ~ 125°C; Package: 0402; Part_Status: In Prod; Tolerance: 10%; Voltage: 50V
C56 = CAP-NP: CAP, CER, 1000PF, 10%, X7R, 50V, 0402; Approved: Approved; CY_PN: 510-60415-01; Device_File: 510-60415-01; Dielectric: X7R; FPLIST: CAPC1005_0402N,CAPC1005_0402M; Lifecycle: Active; Manufacturer: Wurth; Manufacturer_PN: 885012205061; Operating_Temp: -55°C ~ 125°C; Package: 0402; Part_Status: In Des; Tolerance: 10%; Voltage: 50V
D6 = DIO-TVS: DIO, TVS, UNIDIR, 5V, 18.6V, 174W, SOD-523; CY_PN: 530-60165-01; DNI: DNI; Device File: 530-60165-01; Manufacturer: MCC
FB2 = FB: IND, FERRITE BEAD, 120 OHM, 0402; Approved: Approved; CY_PN: 520-60343-01; Current: 500mA; DB_Status: Verified; Device_File: 520-60343-01; FPLIST: INDC1005_0402M,INDC1005_0402N,INDC1005_0402L; Lifecycle: Active; Manufacturer: Wurth; Manufacturer_PN: 74279271; Material: Ferrite; Operating_Temp: -55°C ~ 125°C; Package: 0402; Part_Status: Unrel; Part_Type: Ferrite bead; Tolerance: 25%
J3 = PLG-10-ODD-EVEN-J: HDR, CONN, HEADER, MALE, 1.27mm, 10POS, GOLD, SMD; Approved: Approved; CY_PN: 710-60030-01; Conatct_Length: 3.05mm; Contact_Finish: GOLD; Current_Rating: 3.4A; DNI: DNI; Description1: Unshrouded, Keyed; Device_File: 710-60030-01; Lifecycle: Active; Manufacturer: Samtec Inc.; Manufacturer_PN: FTSH-105-01-L-DV-K; Mated_Height: 6.25mm; Operating_Temp: -55°C to 125°C; Part_Status: InProd; Pin_Pitch: 1.27mm; Pins: 10; Row_pitch: 1.27mm; Rows: 2; Shrouding: NA
J4 = SKT-8-ALT-J: CONN, HDR, FEMALE, SINGLE, 8POS, 2.54mm, GOLD, STR, TH; Approved: Approved; CY_PN: 710-60025-01; Conatct_Length: NA; Contact_Finish: GOLD; Current_Rating: 3A; DNI: DNI; Device_File: 710-60025-01; FPLIST: RTST254P1X08_W265,RTST254P1X08_W265_VER1; Lifecycle: Active; Manufacturer: Sullins; Manufacturer_PN: PPPC081LFBN-RC; Mated_Height: 8.5mm; Operating_Temp: -40°C to 105°C; Part_Status: In Prod; Pin_Pitch: 2.54mm; Pins: 8; Row_pitch: NA; Rows: 1; Shrouding: NA
M1 = BLDC_Motor_1103-KV2230: Motor, BLDC, 6.5VDC, 8Pole, 6.2 OHM, Ke0.21V/kRPM; Approved: Approved; CY_PN: 1103-KV2230; Device_File: 1103-KV2230; Lifecycle: Custom; Manufacturer: SUNNYSKY; Manufacturer_PN: 1103-KV2230; Part_Status: Unrel
R16 = RES: RES, 1 OHM, 1%, 1W, 1210, SMD; Approved: Approved; CY_PN: 500-61348-01; Device_File: 500-61348-01; Lifecycle: Active; Manufacturer: ROHM; Manufacturer_PN: ESR25JZPF1R00; Operating_Temp: -55°C ~ 155°C; Package: 1210; Part_Status: Unrel; Rating: 1W; Tolerance: 1%
R18 = RES: RES, 680K, 1%, 1/16W, 0402; Approved: Approved; CY_PN: 500-61349-01; Device_File: 500-61349-01; FPLIST: RESC1005_0402N,RESC1005_0402M; Lifecycle: Active; Manufacturer: Yageo; Manufacturer_PN: RC0402FR-07680KL; Operating_Temp: -55°C ~ 155°C; Package: 0402; Part_Status: Unrel; Rating: 1/16W; Tolerance: 1%
R19 R21 R31-R33 = RES: RES, FIXED, 1K OHM, 1%, 1/10W, 0402; Approved: Approved; CY_PN: 500-61404-01; Device_File: 500-61404-01; FPLIST: RESC1005_0402N,RESC1005_0402M; Lifecycle: Active; Manufacturer: Wurth; Manufacturer_PN: 560112110012; Operating_Temp: -55°C ~ 155°C; Package: 0402; Part_Status: unrel; Rating: 1/10W; Tolerance: 1%
R20 = POT_1_2_3: RES, POT, 10K OHM, 1/8W, TOP, SMD; Approved: Approved; CY_PN: 500-61347-01; Device_File: 500-61347-01; Lifecycle: Active; Manufacturer: Nidec Copal Electronics; Manufacturer_PN: ST-32ETB103; Operating_Temp: -55°C ~ 125°C; Package: SMD; Part_Status: Unrel; Rating: 1/8W; Tolerance: 20%
R22 R23 = RES: RES, Fixed, 0 OHM, JUMPER, 1/10W, 0603; Approved: Approved; CY_PN: 500-60037-01; Costing: MCU and Power; Device_File: 500-60037-01; FPLIST: RESC1608_0603N,RESC1608_0603Q,RESC1608_0603M; Lifecycle: Active; Manufacturer: Wurth; Manufacturer_PN: 560112116001; Operating_Temp: -55°C ~ 155°C; Package: 0603; Part_Status: In Prod; Rating: 1/10W; Tolerance: JUMPER
R24 R25 = RES: RES, Fixed, 4.7K, 5%, 1/16W, 0402; CY_PN: 500-60095-01; DNI: DNI; Device_File: 500-60095-01; FPLIST: RESC1005_0402N,RESC1005_0402M; Lifecycle: Active; Manufacturer: Yageo; Manufacturer_PN: RC0402JR-074K7L; Operating_Temp: -55°C to 155°C; Package: 0402; Part_Status: In Production; Rating: 1/16W; Tolerance: 5%
R42-R44 = RES: RES, 10K OHM, 1%, 1/20W, 0201; Approved: Approved; CY_PN: 500-61335-01; DNI: DNI; Device_File: 500-61335-01; FPLIST: RESC0603_0201N,RESC0603_0201Q; Lifecycle: Active; Manufacturer: Yageo; Manufacturer_PN: RC0201FR-0710KL; Operating_Temp: -55°C ~ 125°C; Package: 0201; Part_Status: Unrel; Rating: 1/20W; Tolerance: 1%
R51 = RES: RES, Fixed, 0 OHM, JUMPER, 0.5A, 0201; CY_PN: 500-60684-01; Device_File: 500-60684-01; FPLIST: RESC0603_0201N,RESC0603_0201Q; Lifecycle: Active; Manufacturer: Yageo; Manufacturer_PN: RC0201JR-070RL; Operating_Temp: -55°C to 125°C; Package: 0201; Part_Status: In Production; Rating: 0.5A; Tolerance: JUMPER
R59 = RES: RES, 100K OHM, 1%, 1/20W, 0201; Approved: Approved; CY_PN: 500-61334-01; Device_File: 500-61334-01; FPLIST: RESC0603_0201N,RESC0603_0201Q; Lifecycle: Active; Manufacturer: Yageo; Manufacturer_PN: RC0201FR-07100KL; Operating_Temp: -55°C ~ 125°C; Package: 0201; Part_Status: In Des; Rating: 1/20W; Tolerance: 1%
R62 R63 = RES: RES, FIXED, 4.7K OHM, 1%, 100PPM, 1/10W, 0402; Approved: Approved; CY_PN: 500-60246-01; Device_File: 500-60246-01; FPLIST: RESC1005_0402N,RESC1005_0402M; Lifecycle: Active; Manufacturer: Wurth; Manufacturer_PN: 560112110245; Operating_Temp: -55°C ~ 155°C; Package: 0402; Part_Status: unrel; Rating: 1/10W; Tolerance: 1%
R70 = RES: RES, FIXED, 0 OHM, JUMPER, 1A, 1/16W, 0402; Approved: Approved; CY_PN: 500-60344-01; DNI: DNI; Device_File: 500-60344-01; FPLIST: RESC1005_0402N,RESC1005_0402M; Lifecycle: Active; Manufacturer: Wurth; Manufacturer_PN: 560112110001; Operating_Temp: -55°C ~ 155°C; Package: 0402; Part_Status: In Prod; Rating: 1/16W; Tolerance: JUMPER
TH1 = THERMISTOR: RES, THERM, NTC, 100K OHM, 4250K, 0402; Approved: Approved; CY_PN: 500-61286-01; Device_File: 500-61286-01; FPLIST: RESC1005_0402N,RESC1005_0402M; Lifecycle: Active; Manufacturer: Murata; Manufacturer_PN: NCP15WF104D03RC; Operating_Temp: -40°C ~ 125°C; Package: 0402; Part_Status: In design; Rating: 0.1W; Tolerance: 0.05%
TIE1 TIE2 = NET-TIE2: Net Short, Copper Trace; CY_PN: NA; DNI: DNI; Lifecycle: NA; Manufacturer: NA; Manufacturer_PN: NA; Part_Status: NA
TP5 TP8 = TP_SMD: TestPoint, PCB, Circle, 0.75mm, SMD; CY_PN: NA; DNI: DNI; Lifecycle: NA; Manufacturer: NA; Manufacturer_PN: NA; Part_Status: NA
U1 = IC_PSC3M5FDS2LGQ1_VQFN-48: IC, INFINEON, MCU, 32BIT, 256KB FLASH, 64KB SRAM, VQFN-48; Approved: Approved; Description1: IC, INFINEON, MCU, 32BIT, 256KB FLASH, 64KB SRAM, VQFN-48, CORDIC accelerator, 4SCB; FPLIST: VQFN40P600X600X90-49N,VQFN40P600X600X90-49N_NOFID; HARD_LOCATION: YES; Lifecycle: Active; Manufacturer: Infineon; Operating_Temp: -40°C ~ 105°C; Operating_Voltage: 1.7V-3.6V; Package: VQFN-48; Part_Status: Unrel
U3 = IC_IRSM836-024MA: IC, Infineon, IPM, MOTOR DRIVER, 20V, 4A, 250V, 36-PQFN; Approved: Approved; Lifecycle: Active; Manufacturer: Infineon; Operating_Temp: -40°C ~ 150°C; Operating_Voltage: 20V; Package: 36-PQFN; Part_Status: Unrel
C46 C50 = CAP-NP: CAP, CER, 100pF, 5%, C0G, 50V, 0402; Approved: Approved; CY_PN: 510-60558-01; DNI: DNI; Device_File: 510-60558-01; Dielectric: COG; FPLIST: CAPC1005_0402N,CAPC1005_0402M; Lifecycle: Active; Manufacturer: Wurth; Manufacturer_PN: 885012005061; Operating_Temp: -55°C ~ 125°C; Package: 0402; Part_Status: In Prod; Tolerance: 5%; Voltage: 50V
C47 C57 C58 = CAP-NP: CAP, CER, 100pF, 5%, C0G, 50V, 0402; Approved: Approved; CY_PN: 510-60558-01; Device_File: 510-60558-01; Dielectric: COG; FPLIST: CAPC1005_0402N,CAPC1005_0402M; Lifecycle: Active; Manufacturer: Wurth; Manufacturer_PN: 885012005061; Operating_Temp: -55°C ~ 125°C; Package: 0402; Part_Status: In Prod; Tolerance: 5%; Voltage: 50V
C48 C49 = CAP-NP: CAP, CER, 0.1uF, 20%, X5R, 10V, 0201; CY_PN: 510-60777-01; DNI: DNI; Device_File: 510-60777-01; Dielectric: X5R; FPLIST: CAPC0603_0201N,CAPC0603_0201Q; Lifecycle: Active; Manufacturer: Murata; Manufacturer_PN: GRM033R61A104ME84D; Operating_Temp: -55°C to 85°C; Package: 0201; Part_Status: In Des; Tolerance: 20%; Voltage: 10V
D7 = DIO-LED: LED, RED, CLEAR, 625nm, 2V, 0603; Approved: Approved; CY_PN: 534-60120-01; Device_File: 534-60120-01; Lifecycle: Active; Manufacturer: Wurth; Manufacturer_PN: 150060RS75000; Operating_Temp: -40°C to 85°C; Package: 0603; Part_Status: In Prod; Rating: 30mA; Voltage: 2V
R26 = RES: RES, Fixed, 470 OHM, 1%, 1/10W, 0402; Approved: Approved; CY_PN: 500-61405-01; Device_File: 500-61405-01; FPLIST: RESC1005_0402N,RESC1005_0402M; Lifecycle: Active; Manufacturer: Wurth; Manufacturer_PN: 560112110167; Operating_Temp: -55°C ~ 155°C; Package: 0402; Part_Status: unrel; Rating: 1/10W; Tolerance: 1%
R36 R64 R67 = RES: RES, FIXED, 10K OHM, 1%, 1/10W, 0402; Approved: Approved; CY_PN: 500-60461-01; Device_File: 500-60461-01; FPLIST: RESC1005_0402N,RESC1005_0402M; Lifecycle: Active; Manufacturer: Wurth; Manufacturer_PN: 560112110020; Operating_Temp: -55°C ~ 155°C; Package: 0402; Part_Status: unrel; Rating: 1/10W; Tolerance: 1%
R37 = RES: RES, FIXED, 47K OHM, 1%, 1/10W, 0402; Approved: Approved; CY_PN: 500-61406-01; Device_File: 500-61406-01; FPLIST: RESC1005_0402N,RESC1005_0402M; Lifecycle: Active; Manufacturer: Wurth; Manufacturer_PN: 560112110055; Operating_Temp: -55°C ~ 155°C; Package: 0402; Part_Status: unrel; Rating: 1/10W; Tolerance: 1%
R38 = RES: RES, 9.1K OHM, 1%, 1/10W, 0402, SMD; Approved: Approved; CY_PN: 500-60569-01; Device_File: 500-60569-01; FPLIST: RESC1005_0402N,RESC1005_0402M; Lifecycle: Active; Manufacturer: Panasonic; Manufacturer_PN: ERJ-2RKF9101X; Operating_Temp: -55°C ~ 155°C; Package: 0402; Rating: 1/10W; Tolerance: 1%; Wattage: 1/10W
R61 R66 = RES: RES, FIXED, 910 OHM, 1%, 1/10W, 0402, SMD; Approved: Approved; CY_PN: 500-60572-01; Device_File: 500-60572-01; FPLIST: RESC1005_0402N,RESC1005_0402M; Lifecycle: Active; Manufacturer: Panasonic; Manufacturer_PN: ERJ-2RKF9100X; Operating_Temp: -55°C ~ 155°C; Package: 0402; Part_Status: In Prod; Rating: 1/10w; Tolerance: 1%
R68 R69 = RES: RES, FIXED, 20K, 1%, 1/16W, 0402; Approved: Approved; CY_PN: 500-60900-01; Device_File: 500-60900-01; FPLIST: RESC1005_0402N,RESC1005_0402M; Lifecycle: Active; Manufacturer: Yageo; Manufacturer_PN: RC0402FR-0720KL; Operating_Temp: -55°C ~ 155°C; Package: 0402; Part_Status: In Prod; Rating: 1/16W; Tolerance: 1%
SW1 = SWITCH-PB-12-34-G56: SW, Tactile Switch SPST-NO, TOP Actuated SMD; Actuator_Length: 0.4mm; Approved: Approved; CY_PN: 770-60161-01; Circuit: SPST-NO; Current_Rating: 0.05A; HARD_LOCATION: YES; Lifecycle: Active; Manufacturer: Wurth; Operating_Force: 160gf; Operating_Temp: -40°C ~ 85°C; Part_Status: Unrel; Pins: 6; Switch_Function: Off-Mom
SW2 = SWITCH-PB-12-34-G56: SW, Tactile Switch SPST-NO, TOP Actuated SMD; Actuator_Length: 0.4mm; Approved: Approved; CY_PN: 770-60161-01; Circuit: SPST-NO; Current_Rating: 0.05A; Lifecycle: Active; Manufacturer: Wurth; Operating_Force: 160gf; Operating_Temp: -40°C ~ 85°C; Part_Status: Unrel; Pins: 6; Switch_Function: Off-Mom
U6 = IC_AD8615AUJZ: IC, OPAMP, GP, 1CKT, 2.7V-5.5V, 24MHz, R-to-R, SOT-23-5; Approved: Approved; CY_PN: 450-60487-01; Device_File: 450-60487-01; Lifecycle: Active; Manufacturer: Analog devices; Operating_Temp: -40°C ~ 125°C; Operating_Voltage: 2.7V-5.5V; Package: SOT-23-5; Part_Status: Unrel
ACC16 = LABEL: LBL, PCA Label, Vendor Code, Datecode, Serial Number (YYWWVVXXXXX); CY_PN: 899-60120-01; Costing: Accessories; Device File: 899-60120-01; Manufacturer: JETech; Manufacturer_PN: 899-60120-01; Operating_Temp: NA; Part_Status: In Prod
ACC17 = LABEL: LBL, QR CODE, 10mm X 10mm, PSoC Control C3M5 Compact Kit; CY_PN: 899-60352-01; Costing: Accessories; Manufacturer: JETech
ACC18 = SCREW_DRIVER: HW, Screwdriver, Cross-Head Screw Driver for Raspberry Pi, Length-85mm; CY_PN: 700-60223-01; Description1: HW, Screwdriver, Cross-Head Screw Driver for Raspberry Pi, Length-85mm, Material-steel, Handle-Plastic; Manufacturer: Raspberry Pi; Manufacturer_PN: [53599] Cross-Head Screw Driver for Raspberry Pi; Operating_Temp: NA; Part_Status: Unrel
ACC19-ACC21 = SCREW: HW, Screw, M1.2 X 0.25 X 3, PAN (+), MC Micro, SS-304; CY_PN: 700-60224-01; Manufacturer: McMaster-Carr; Manufacturer_PN: B4B0410203; Operating_Temp: NA; Part_Status: Unrel
ACC22 = LABEL_2: LBL, SEGGER LOGO, 10mm X 5mm, PSoC Control C3M5 Compact Kit; CY_PN: 899-60359-01; Costing: Accessories; Manufacturer: JETech

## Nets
15V_OUT: C1.1 C2.1 C3.1 C4.1 C5.1 C23.1 D2.K R1.1 R18.1 R70.2 TP10.1(TP) U3.34(VCC)
GND_EARTH: C11.1 J1.SH1 J1.SH2 R3.1
GND_SIGNAL: C2.2 C3.2 C4.2 C5.2 C6.2 C7.2 C8.2 C9.2 C10.2 C11.2 C12.2 C13.2 C14.2 C15.2 C16.2 C17.2 C18.2 C19.2 C20.2 C21.2 C22.2 C23.2 C24.2 C28.2 C30.2 C31.2 C32.2 C33.2 C34.2 C35.2 C36.2 C37.2 C38.2 C39.2 C40.2 C41.2 C42.2 C43.2 C44.2 C45.1 C46.2 C47.2 C48.1 C49.1 C51.2 C52.1 C53.2 C56.2 C57.2 C58.2 D3.K(CATHODE) D4.3(GND) D6.A(ANODE) J1.4(GND) J2.5 J3.3 J3.5 J3.7 J4.4 R3.2 R4.2 R10.2 R16.2 R20.1(CCW) R38.2 R69.2 SW1.3 SW1.4 SW1.5(GND) SW1.6(GND) SW2.3 SW2.4 SW2.5(GND) SW2.6(GND) TH1.2 TIE2.1(N1) TP2.1(TP) TP9.1(TP) TP12.1(TP) U1.H(VSS) U2.11(P14.7) U2.12(P14.6) U2.13(P14.5) U2.14(P14.4) U2.15(P14.3) U2.16(P14.0) U2.17(VSSA/VAGND) U2.20(P14.8) U2.27(VSS) U2.H(VSS) U3.9(VSS/COM_1) U3.39(VSS/COM_2) U4.3(GND) U4.6(RADJ) U4.H(EPAD) U5.2(PGND) U6.2(V-) U7.3(GND) Y1.2(GND_1) Y1.4(GND_2)
VBUS: C6.1 C7.1 D1.K L1.1 R7.1 R8.2 R71.2 TP11.1(TP) U4.1(IN) U4.4(EN) U5.4(EN) U5.5(VIN)
VCC_3V3: C8.1 C9.1 C45.2 C52.2 D6.K(CATHODE) D7.A(ANODE) D8.A(ANODE) FB2.1 J2.1 J3.1 J4.1 R5.1 R20.3(CW) R22.1 R24.1 R25.1 R42.1 R43.1 R44.1 R47.1 R50.2 R52.1 R62.1 R64.1 R67.1 R68.1 TP3.1(TP) U4.7(ADJ/FB) U4.8(Q) U6.5(V+) U7.5(VCC)
VCCD: C43.1 U1.5(VCCD)
VDDA: C33.1 C34.1 FB2.2 R23.1 R59.1 U1.41(VDDA)
VDDC: C15.1 C16.1 C17.1 U2.6(VDDC) U2.31(VDDC)
AN_B2: J4.2 U1.38(AN_B2)
AN_B3: J4.3 U1.39(AN_B3)
CS: U2.23(P2.3) U2.40(P1.0)
Debug_LED: D9.K(CATHODE) U2.48(P0.2)
EN_IPM: R63.1 U1.7(P0.0)
GK_IPM: C56.1 D10.K R48.2 R62.2 TP8.1(TP) U3.5(FLT_N)
IDC_LINK_OPAMP: C47.1 R32.2 U1.33(AN_A2)
IDC_LINK_PSEUDO_N: C57.1 R66.2 R67.2 U1.32(AN_A1)
IDC_LINK_PSEUDO_P: C58.1 R61.2 R64.2 U1.31(AN_A0)
IPM_V+: C24.1 R37.1 R70.1 R71.1 TP4.1(TP) U3.22(V+_1) U3.23(V+_2) U3.24(V+_3) U3.25(V+_4) U3.26(V+_5) U3.27(V+_6) U3.28(V+_7) U3.29(V+_8)
IU: R31.1 R61.1 TIE1.2(N2)
IU0: R33.1 R66.1 TIE2.2(N2)
M_SPEED_POT: R21.1 U1.42(AN_B4)
OBD_PORST_L: J2.4 R50.1 R51.1 U2.32(\~{PORST})
OBD_TCK: J2.2 U2.34(TCK)
OBD_TMS: J2.3 U2.33(TMS)
OBD_UART_RX: R9.2 U2.46(P0.4)
OBD_UART_TX: R11.2 U2.45(P0.5)
OBD_USB_DM: D4.1(IN1) J1.2(DM) R14.1
OBD_USB_DP: D4.2(IN2) J1.3(DP) R13.1
OBD_VDDA: C12.1 C18.1 C19.1 C20.1 C21.1 C22.1 R5.2 U2.5(VDDP) U2.10(VBAT) U2.18(VDDA/VAREF) U2.28(VDDP) U2.41(VDDP)
P8_0: J4.5 U1.43(P8.0)
P8_1: J4.6 R24.2 U1.44(P8.1)
P8_2: J4.7 U1.45(P8.2)
P8_3: J4.8 R25.2 U1.46(P8.3)
PSC3_UART_RX: R11.1 U1.1(P9.2)
PSC3_UART_TX: R9.1 U1.2(P9.3)
PWMUH: U1.20(P4.5) U3.35(HIN1)
PWMUL: U1.17(P4.2) U3.2(LIN1)
PWMVH: U1.19(P4.4) U3.36(HIN2)
PWMVL: U1.16(P4.1) U3.3(LIN2)
PWMWH: U1.18(P4.3) U3.1(HIN3)
PWMWL: U1.15(P4.0) U3.4(LIN3)
SWD_DIR: U2.37(P1.3) U7.1(OE)
SWD_OUT: U2.35(P1.5) U7.2(A)
SWDCLK: J3.4 R39.2 R43.2 U1.8(P1.2) U2.22(P2.4)
SWDIO: J3.2 R40.2 R44.2 R52.2 U1.9(P1.3) U7.4(Y)
TDO: J3.6 R42.2 U1.11(P2.1)
TEMP: C53.1 R59.2 TH1.1 U1.34(AN_A3)
U: M1.U U3.10(U/VS1_1) U3.11(U/VS1_2)
USER_LED1: R26.1 U1.28(P7.0)
USER_LED2: R29.1 U1.47(P9.0)
USER_SW: C48.2 R34.2 SW2.1 SW2.2 U1.21(P4.6)
V: C26.2 M1.V U3.16(V/VS2_1) U3.17(V/VS2_2)
V_TRIP: C30.1 R19.2 TP5.1(TP) U3.6(ITRIP)
VB1: C25.2 U3.31(VB1)
VB2: C26.1 U3.32(VB2)
VB3: C27.1 U3.33(VB3)
VBACKUP: C31.1 C32.1 C35.1 C36.1 C37.1 C38.1 C39.1 C40.1 C41.1 C42.1 R22.2 R34.1 R35.1 U1.4(VDDD) U1.6(VBACKUP) U1.12(VDDIO_0_0) U1.24(VDDIO_0_1) U1.48(VDDIO_1)
VDC_LINK: C51.1 R37.2 R38.1 U1.35(AN_A4)
VREF_EXT: C44.1 R23.2 U1.40(VAREF_EXT)
W: C27.2 M1.W U3.18(W/VS3_1) U3.19(W/VS3_2)
XRES_L_MCU: C49.2 J3.10 R35.2 R53.1 SW1.1 SW1.2 U1.3(XRES)
XTAL1: C13.1 U2.29(XTAL1) Y1.1
XTAL2: C14.1 R12.1 Y1.3
N07345: FB1.1 J1.1(VBUS)
N07349: C10.1 D1.A FB1.2
N08163: D2.A L1.2 U5.1(SW)
N11111: R14.2 U2.3(USB_DM)
N20632: C1.2 R1.2 R4.1 U5.3(FB)
N32254: R12.2 U2.30(XTAL2)
N37178: C28.1 R18.2 U3.8(RCIN)
N38243: C25.1 U3.30(U/VS1_3)
N38502: R16.1 R19.1 TIE1.1(N1) U3.12(VR1_1) U3.13(VR1_2) U3.14(VR2_1) U3.15(VR2_2) U3.20(VR3_1) U3.21(VR3_2)
N50220: R8.1 R10.1 U2.7(HIB_IO_0)
N86492: D3.A(ANODE) R7.2
N117783: C46.1 R31.2 R68.2 R69.1 U6.3(+)
N117862: C50.1 R33.2 R36.1 U6.4(-)
N117920: C50.2 R32.1 R36.2 U6.1(OUT)
N133373: D7.K(CATHODE) R26.2
N133421: D8.K(CATHODE) R29.2
N143868: R20.2(WIPER) R21.2
N214953: R39.1 U2.39(P1.1)
N215126: R40.1 U2.36(P1.4)
N223602: J3.9 R51.2
N254765: R53.2 U2.47(P0.3)
N255191: D9.A(ANODE) R47.2
N338896: D10.A R63.2 U3.7(EN)
N367460: R13.2 U2.4(USB_DP)
N371560: R48.1 U1.10(P2.0)

Not connected (* = marked no-connect by the designer): J3 8*; U1 13(P2.2)* 14(P2.3)* 22(P4.7)* 23(P6.0)* 25(P6.1)* 26(P6.2)* 27(P6.3)* 29(P7.1)* 30(P7.2)* 36(AN_A5)* 37(AN_B1)*; U2 1(P0.1)* 2(P0.0)* 8(RTC_XTAL1)* 9(RTC_XTAL2)* 19(P14.9)* 21(P2.5)* 24(P2.2)* 25(P2.1)* 26(P2.0)* 38(P1.2)* 42(P0.8)* 43(P0.7)* 44(P0.6)*; U4 2(NC)* 5(RO)*

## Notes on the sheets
sheet 1
- REVISION HISTORY
- REV
- ORIG. OF
  CHANGE
- DATE
- DESCRIPTION OF CHANGE
- 01
- Initial Internal Revision
- SAMANTH
- 03/07/2024
- 02
- Initial release
- SAMANTH
- 10/09/2024
sheet 2
- Accessories
- PCBA Labels
- Screw Driver
- Screws for Motor Assembly
sheet 3
- KIT_PSC3M5_2GO
- PSOC™ Control C3M5 Compact Kit
- CONTENTS
- PAGE
- DESCRIPTION
- 01
- Title, Table of Contents & Drawing Numbers
- 02
- Functional Block Diagram
- 03
- Power Supply & XMC4200 Bridge
- 04
- PSOC™ C3M5 Device IOs & Headers
- 05
- Current Sense, Switches & LEDs
- 06
- Accessories
- 07
- Revision History
- Drawing Numbers
- PCBA
- PCB
- FAB DRW
- ASSY DRW
- SCH DRW
sheet 5
- USB 2.0 Type-A Plug
- 5V to 15V Boost Power Supply
- 3.3V LDO
- 5V, 500mA
- 15V, 200mA
- 3.3V, 200mA
- Input --> 2.7V - 18V
  Output --> 3.3V
  IDC --> 800mA
  Iq --> 90uA
- XMC4200 Debugger: USB -->UART Bridge
- Keep GND loop small as possible
- Crystal
- XMC4200 SWD Header
- Power LED
- Place D4 close to the source of ESD
- XMC4200 Decoupling capacitors
sheet 6
- PSOC™ Control C3M5 Device
- IPM: Motor Driver Control
- 15V, 200mA
- Keep IU and IU0 in differential pair towards U6 (OP-AMP)
  Follow kelvin method
  VTRIP can be a single ended routing
- Potentiometer
- PSOC™ Control C3M5 Device
  Decoupling capacitors
- PSOC™ Control C3M5 Device Power
- Cortex Debug Connector
- GPIO Header
sheet 7
- USER LEDs
- IDC LINK - Single Shunt Current Sense
- User Switch
- Reset Switch
- IU and IU0 nets should be differential pair
  (Follow 4-wire Kelvin method).
- Keep IU loop very small
- Reset switch on PCB top
- Single Shunt Current Sensing
  Offset --> 1.65V
  R sense --> 1E
  Gain -->10
- R32 and C47 (RC) should be close
  to ADC pin of PSC3M5 device
- VDC LINK - Phase voltage Sense
- R64 and C58 (RC) should be close
  to ADC pin of PSC3M5 device
- IU and IU0 nets should be differential pair
- R67 and C57 (RC) should be close
  to ADC pin of PSC3M5 device
